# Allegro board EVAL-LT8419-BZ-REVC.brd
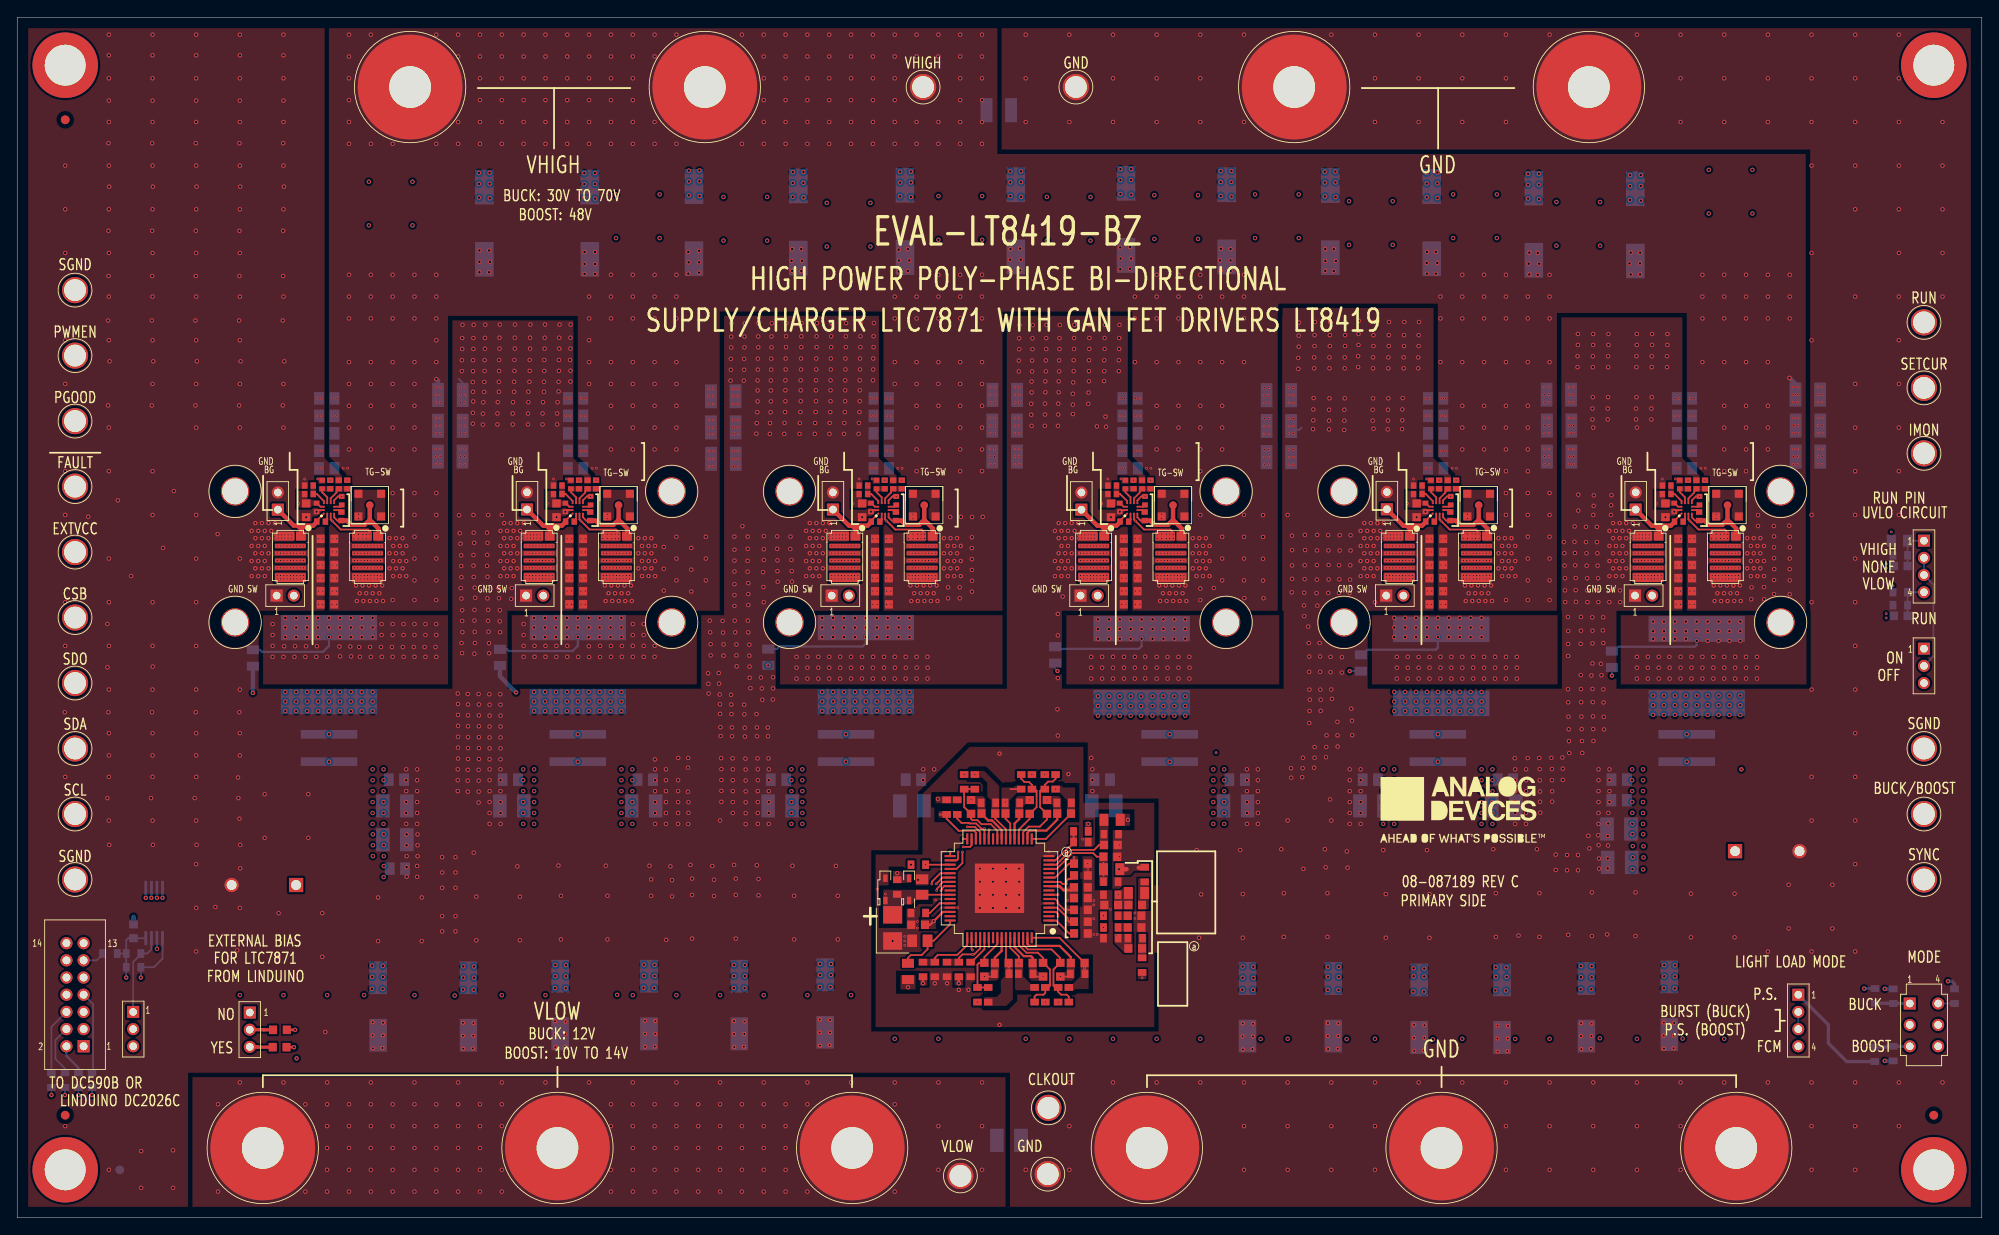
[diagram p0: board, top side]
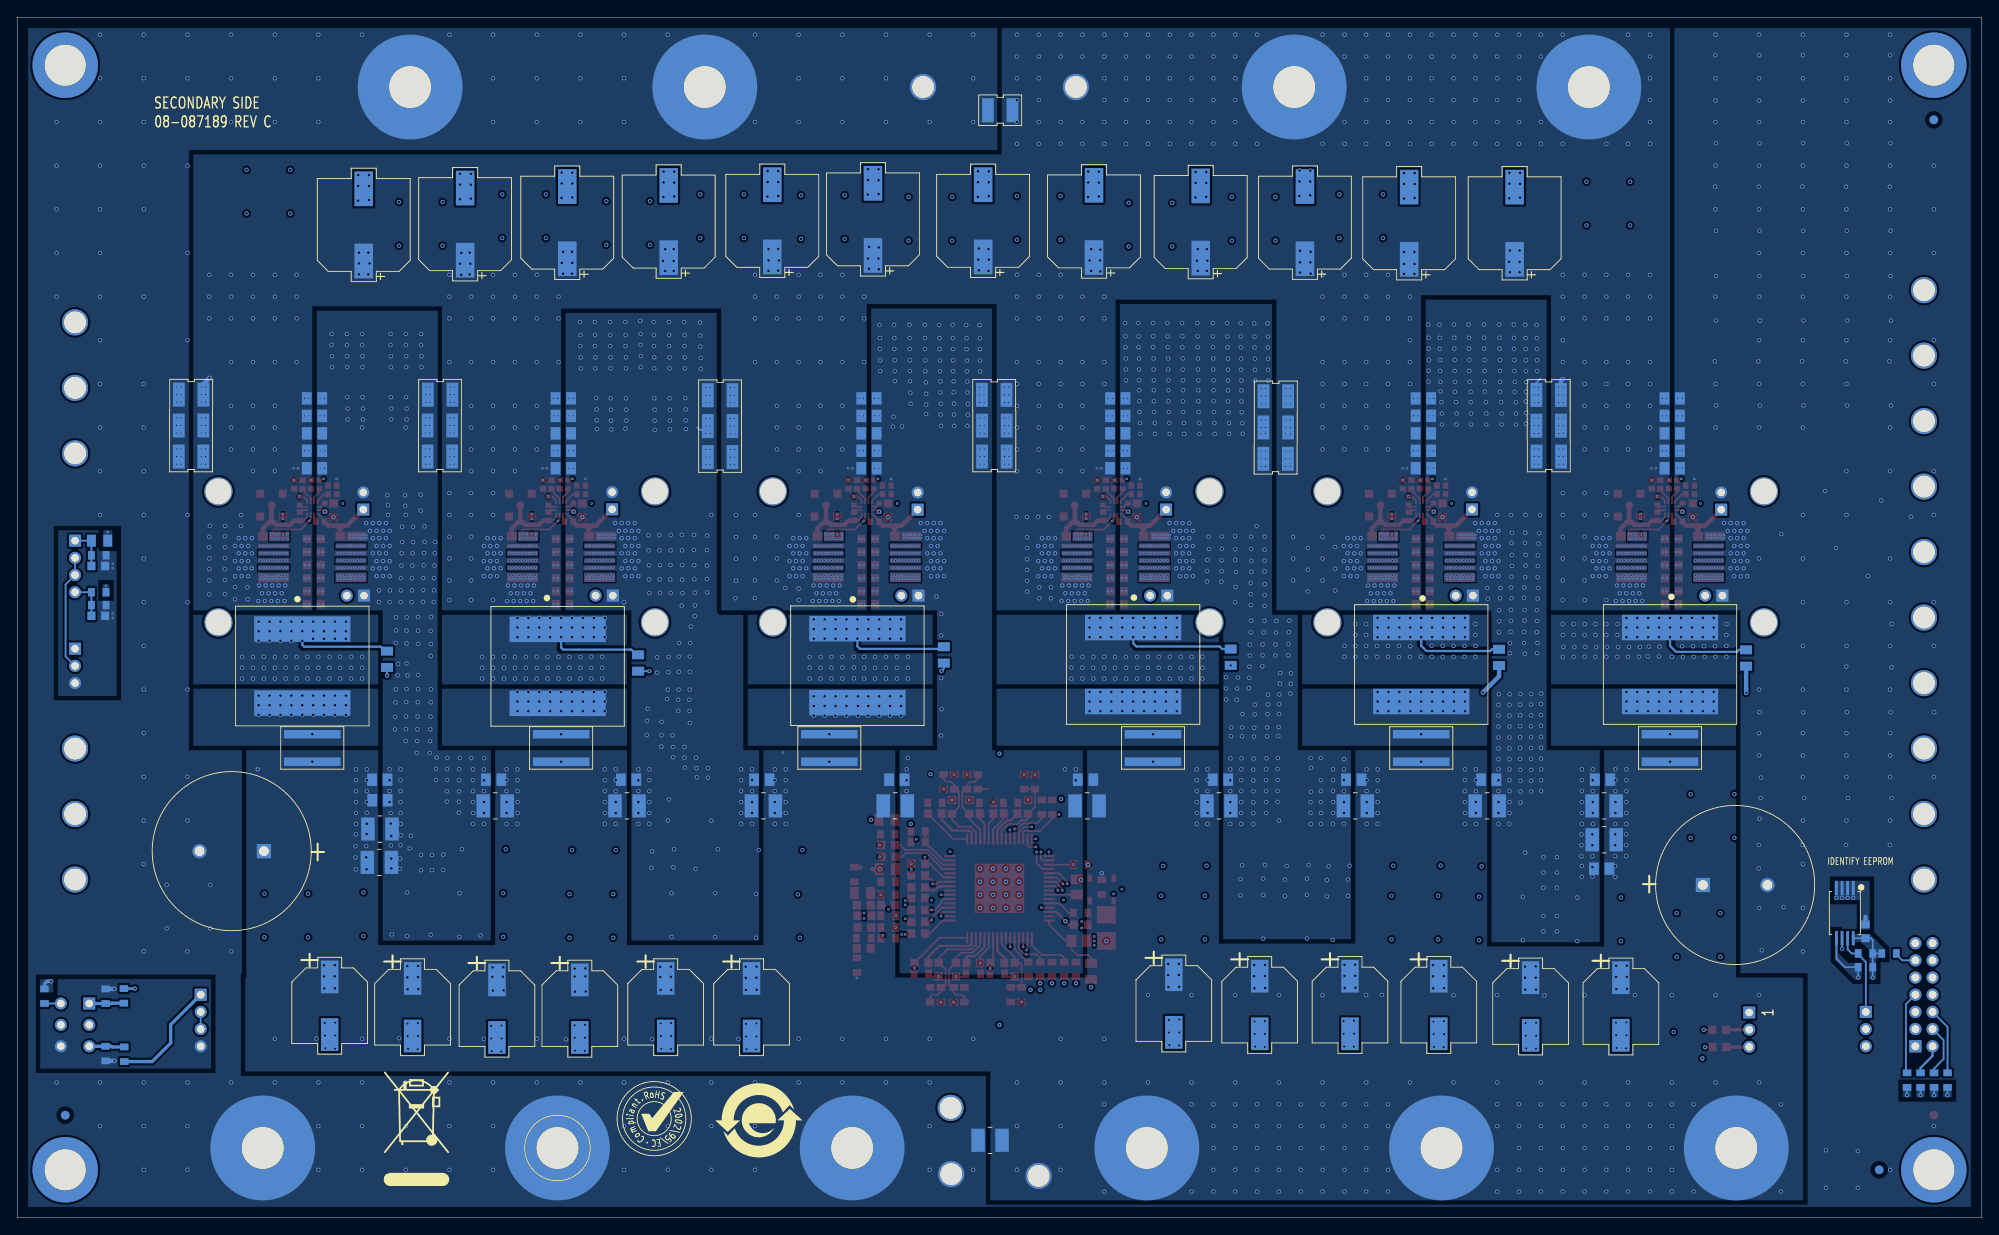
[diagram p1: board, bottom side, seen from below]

Outline 228.6 x 139.7 mm; copper layers: TOP, L2_PWR, L3_PWR, L4_PWR, L5_GND, L6_SIG, L7_SIG, BOTTOM. Coordinates in mm from the lower left corner of the outline.
Outline path: 0,139.7 0,0 228.6,0 228.6,139.7 0,139.7

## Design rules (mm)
constraint set DEFAULT: min track width 0.203
net group 3.3V_5V: nets 3.3V_5V SDO
net group _N108: nets _N108 _N113
net group SAC1: nets _N123 SDC1
net group SAC2: nets _N160 SDC2
net group SAC3: nets _N192 SDC3
net group SAC4: nets _N208 SDC4
net group SAC5: nets _N216 SDC5
net group SAC6: nets _N224 SDC6
net group _N125: nets _N125
net group _N126: nets _N126
net group _N161: nets _N161
net group _N162: nets _N162
net group _N193: nets _N193
net group _N194: nets _N194
net group _N209: nets _N209
net group _N210: nets _N210
net group _N217: nets _N217
net group _N218: nets _N218
net group _N225: nets _N225
net group _N226: nets _N226
net group CSB: nets _N101
net group PGOOD: nets _N69 _N265 _N266 _N267
net group PWM1: nets PWM1
net group PWM2: nets PWM2
net group PWM3: nets PWM3
net group PWM4: nets PWM4
net group PWM5: nets PWM5
net group PWM6: nets PWM6
net group SCL: nets _N100
net group SDA: nets _N102

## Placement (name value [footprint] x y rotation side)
C1  0.1UF  [C0402]  34.83 82.65 270 top
C2  1uF  [C0805]  105.3 38.49 90 top
C3  4.7uF  [C0603]  33.62 82.32 270 top
C4  10pF  [C0402]  35.48 85.33 270 top
C5  47PF  [C0603]  123.77 34.46 180 top
C6  0.01uF  [C0603]  130.02 33.78 180 top
C7  0.01uF  [C0603]  130.02 35.15 180 top
C8  0.22uF  [C0603]  36.1 77.48 0 top
C9  0.1uF  [C0603]  123.77 33.09 180 top
C10  4.7UF  [C0603]  123.77 37.2 0 top
C11  47pF  [C0603]  123.77 35.83 180 top
C12  10PF  [C0603]  123.77 39.84 0 top
C13  1uF  [C0805]  36.02 93.31 180 bottom
C14  0.1uF  [C0603]  119.83 47.81 90 top
C16  1uF  [C0805]  36.02 91.28 180 bottom
C17  0.1uF  [C0805]  44.24 40.63 0 bottom
C18  5100UF  [CPLRAD295D709H1240LD31]  32.45 38.72 180 bottom
C19  0.1uF  [C0805]  44.13 50.98 0 bottom
C20  5100UF  [CPLRAD295D709H1240LD31]  199.89 42.66 0 bottom
C21  4.7uF  [C1210-2]  43.94 43.99 0 bottom
C22  4.7UF  [C1210H110]  50.4 92.17 0 bottom
C23  4.7uF  [C1210-2]  43.95 47.93 0 bottom
C24  4.7UF  [C1210H110]  50.39 88.58 0 bottom
C25  47UF  [CPLSMSQ327H461]  42 24.59 270 bottom
C26  4.7UF  [C1210H110]  50.4 95.75 0 bottom
C27  47UF  [CPLSMSQ327H461]  52.5 24.59 270 bottom
C28  47UF  [CPLSMSQ327H461]  172.78 24.33 270 bottom
C29  47UF  [CPLSMSQ327H461]  73.52 24.76 270 bottom
C30  47UF  [CPLSMSQ327H461]  63.18 24.76 270 bottom
C31  4.7UF  [C0603]  104.83 34.1 180 top
C32  47UF  [CPLSMSQ327H461]  84.02 24.76 270 bottom
C33  47UF  [CPLSMSQ327H461]  94.01 24.93 270 bottom
C34  47UF  [CPLSMSQ327H461]  182.59 24.5 270 bottom
C35  47UF  [CPLSMSQ327H461]  192.24 24.68 270 bottom
C36  47UF  [CPLSMSQ327H461]  153.14 24.5 270 bottom
C37  47UF  [CPLSMSQ327H461]  143.15 24.5 270 bottom
C38  47UF  [CPLSMSQ327H461]  163.13 24.33 270 bottom
C39  1uF  [C0805]  105.03 32.23 180 top
C40  47UF  [CPLSMSQ406H425]  164.59 115.79 90 bottom
C41  47UF  [CPLSMSQ406H425]  176.48 115.62 90 bottom
C42  47UF  [CPLSMSQ406H425]  188.28 115.53 90 bottom
C43  0.1uF  [C0603]  30.57 21.87 180 top
C44  0.1uF  [C0603]  30.54 19.86 180 top
C45  47UF  [CPLSMSQ406H425]  129.03 116.18 90 bottom
C46  47UF  [CPLSMSQ406H425]  116.2 116.01 90 bottom
C47  47UF  [CPLSMSQ406H425]  103.3 115.94 90 bottom
C48  47UF  [CPLSMSQ406H425]  90.89 115.87 90 bottom
C49  47UF  [CPLSMSQ406H425]  78.76 115.8 90 bottom
C50  47UF  [CPLSMSQ406H425]  66.63 115.73 90 bottom
C51  47UF  [CPLSMSQ406H425]  152.79 115.92 90 bottom
C52  47UF  [CPLSMSQ406H425]  140.74 116.01 90 bottom
C53  47UF  [CPLSMSQ406H425]  54.36 115.73 90 bottom
C56  0.22uF  [C0603]  100.63 71.37 0 top
C65  4.7uF  [C1210-2]  115.4 9.02 0 bottom
C66  4.7UF  [C1210H110]  114.22 128.87 0 bottom
C148  TBD0603  [C0603]  123.77 41.21 0 top
C166  TBD0603  [C0603]  130.09 31.34 180 top
C167  TBD0603  [C0603]  130.09 36.4 180 top
C168  1uF  [C3528]  101.87 33.73 270 top
C169  0.1uF  [C0603]  13.54 33.34 90 bottom
C189  47PF  [C0603]  127.2 42.01 0 top
C194  TBD0603  [C0603]  219.16 70.05 180 bottom
C195  TBD0603  [C0603]  127.3 36.4 180 top
C196  TBD0603  [C0603]  127.25 43.38 0 top
C197  TBD0603  [C0603]  219.16 75.84 180 bottom
C700  0.1uF  [C0603]  123.77 38.45 0 top
C701  0.22uF  [C0402]  37.77 83.44 90 top
C702  0.22uF  [C0603]  36.1 71.38 0 top
C703  0.22uF  [C0603]  36.1 74.43 0 top
C704  0.22uF  [C0603]  36.1 75.95 0 top
C705  0.22uF  [C0603]  36.1 72.92 0 top
C708  1uF  [C0805]  36.02 89.25 180 bottom
C709  1uF  [C0805]  36.02 87.22 180 bottom
C710  1uF  [C0805]  36.02 95.34 180 bottom
C713  0.22uF  [C0603]  36.1 79 0 top
C715  0.1UF  [C0603]  121.82 47.04 180 top
C716  10pF  [C0402]  64.43 85.33 270 top
C717  4.7uF  [C0603]  62.75 82.32 270 top
C718  0.1UF  [C0402]  63.78 82.65 270 top
C719  0.22uF  [C0402]  66.72 83.44 90 top
C720  0.22uF  [C0603]  65.05 72.91 0 top
C721  0.22uF  [C0603]  65.05 71.38 0 top
C722  0.22uF  [C0603]  65.05 75.95 0 top
C723  0.22uF  [C0603]  65.05 74.43 0 top
C724  0.22uF  [C0603]  65.05 79 0 top
C725  0.22uF  [C0603]  65.05 77.48 0 top
C730  1uF  [C0805]  64.97 89.25 180 bottom
C731  1uF  [C0805]  64.97 91.28 180 bottom
C732  1uF  [C0805]  64.97 93.31 180 bottom
C733  1uF  [C0805]  64.97 95.34 180 bottom
C734  1uF  [C0805]  64.97 87.22 180 bottom
C739  4.7UF  [C1210H110]  82.18 88.32 0 bottom
C740  4.7UF  [C1210H110]  82.16 91.96 0 bottom
C741  4.7UF  [C1210H110]  82.15 95.59 0 bottom
C742  0.1UF  [C0603]  115.8 47.04 0 top
C743  0.1uF  [C0603]  117.82 47.81 90 top
C744  0.1uF  [C0805]  57.38 50.98 180 bottom
C745  0.1uF  [C0805]  73.08 50.98 0 bottom
C746  4.7uF  [C1210-2]  57.56 47.93 180 bottom
C747  4.7uF  [C1210-2]  72.9 47.93 0 bottom
C750  10pF  [C0402]  99.99 85.33 270 top
C751  4.7uF  [C0603]  98.32 82.32 270 top
C752  0.1UF  [C0402]  99.35 82.65 270 top
C753  0.22uF  [C0402]  102.28 83.44 90 top
C754  0.22uF  [C0603]  129.57 71.38 0 top
C755  0.22uF  [C0603]  100.62 75.95 0 top
C757  0.22uF  [C0603]  100.62 74.43 0 top
C758  0.22uF  [C0603]  100.62 72.91 0 top
C759  0.22uF  [C0603]  129.57 75.95 0 top
C764  1uF  [C0805]  100.54 89.25 180 bottom
C765  1uF  [C0805]  100.54 91.28 180 bottom
C766  1uF  [C0805]  100.54 95.34 180 bottom
C767  1uF  [C0805]  100.54 93.31 180 bottom
C768  1uF  [C0805]  100.54 87.22 180 bottom
C773  4.7UF  [C1210H110]  114.9 88.58 0 bottom
C774  4.7UF  [C1210H110]  114.9 92.17 0 bottom
C775  4.7UF  [C1210H110]  114.92 95.76 0 bottom
C776  0.1UF  [C0603]  113.01 47.04 180 top
C777  0.1uF  [C0805]  88.59 50.98 180 bottom
C778  0.1uF  [C0805]  104.29 50.98 0 bottom
C779  4.7uF  [C1210-2]  88.77 47.93 180 bottom
C780  4.7uF  [C1210-2]  104.11 47.93 0 bottom
C783  0.1uF  [C0603]  110.99 47.81 90 top
C800  10pF  [C0402]  128.94 85.33 270 top
C801  4.7uF  [C0603]  127.27 82.32 270 top
C802  0.1UF  [C0402]  128.3 82.65 270 top
C803  0.22uF  [C0402]  131.23 83.44 90 top
C804  0.22uF  [C0603]  165.13 77.48 0 top
C805  0.22uF  [C0603]  129.57 79 0 top
C806  0.22uF  [C0603]  129.57 77.48 0 top
C807  0.22uF  [C0603]  165.13 79 0 top
C808  0.22uF  [C0603]  129.57 72.91 0 top
C809  0.22uF  [C0603]  129.57 74.43 0 top
C814  1uF  [C0805]  129.49 91.28 180 bottom
C815  1uF  [C0805]  129.49 89.25 180 bottom
C816  1uF  [C0805]  129.49 87.22 180 bottom
C817  1uF  [C0805]  129.49 95.34 180 bottom
C818  1uF  [C0805]  129.49 93.31 180 bottom
C823  4.7UF  [C1210H110]  146.81 92.13 0 bottom
C824  4.7UF  [C1210H110]  146.81 88.51 0 bottom
C825  4.7UF  [C1210H110]  146.81 95.71 0 bottom
C826  0.1UF  [C0603]  114.56 29.65 180 top
C827  0.1uF  [C0603]  112.54 28.87 270 top
C828  0.1uF  [C0805]  126.25 50.98 180 bottom
C829  0.1uF  [C0805]  141.95 50.98 0 bottom
C830  4.7uF  [C1210-2]  126.43 47.93 180 bottom
C831  4.7uF  [C1210-2]  141.77 47.93 0 bottom
C834  10pF  [C0402]  164.51 85.33 270 top
C835  4.7uF  [C0603]  162.83 82.32 270 top
C836  0.1UF  [C0402]  163.86 82.65 270 top
C837  0.22uF  [C0402]  166.8 83.44 90 top
C838  0.22uF  [C0603]  165.13 74.43 0 top
C839  0.22uF  [C0603]  165.13 71.38 0 top
C840  0.22uF  [C0603]  194.08 71.38 0 top
C841  0.22uF  [C0603]  165.13 72.91 0 top
C842  0.22uF  [C0603]  194.08 74.43 0 top
C843  0.22uF  [C0603]  194.08 75.95 0 top
C848  1uF  [C0805]  165.06 93.31 180 bottom
C849  1uF  [C0805]  165.06 91.28 180 bottom
C850  1uF  [C0805]  165.06 89.25 180 bottom
C851  1uF  [C0805]  165.06 87.22 180 bottom
C852  1uF  [C0805]  165.06 95.34 180 bottom
C857  4.7UF  [C1210H110]  179.42 92.19 0 bottom
C858  4.7UF  [C1210H110]  179.42 88.58 0 bottom
C859  4.7UF  [C1210H110]  179.39 95.78 0 bottom
C860  0.1UF  [C0603]  117.35 29.65 0 top
C861  0.1uF  [C0603]  119.37 28.87 270 top
C862  0.1uF  [C0805]  157.46 50.98 180 bottom
C863  0.1uF  [C0805]  173.16 50.98 0 bottom
C864  4.7uF  [C1210-2]  157.64 47.93 180 bottom
C865  4.7uF  [C1210-2]  172.98 47.93 0 bottom
C868  10pF  [C0402]  193.46 85.33 270 top
C869  4.7uF  [C0603]  191.78 82.32 270 top
C870  0.1UF  [C0402]  192.81 82.65 270 top
C871  0.22uF  [C0402]  195.75 83.44 90 top
C873  0.22uF  [C0603]  194.08 77.48 0 top
C874  0.22uF  [C0603]  194.08 79 0 top
C875  0.22uF  [C0603]  165.13 75.95 0 top
C876  0.22uF  [C0603]  194.08 72.91 0 top
C877  0.22uF  [C0603]  100.62 79 0 top
C878  0.22uF  [C0603]  100.62 77.48 0 top
C883  1uF  [C0805]  194.01 93.31 180 bottom
C884  1uF  [C0805]  194.01 91.28 180 bottom
C885  1uF  [C0805]  194.01 89.25 180 bottom
C886  1uF  [C0805]  194.01 87.22 180 bottom
C887  1uF  [C0805]  194.01 95.34 180 bottom
C892  4.7UF  [C1210H110]  208.37 88.58 0 bottom
C893  4.7UF  [C1210H110]  208.37 92.19 0 bottom
C894  4.7UF  [C1210H110]  208.35 95.79 0 bottom
C895  0.1uF  [C0603]  121.38 28.87 270 top
C896  0.1UF  [C0603]  123.4 29.65 180 top
C897  0.1uF  [C0805]  186.41 50.98 180 bottom
C898  0.1uF  [C0805]  186.39 48.59 180 bottom
C899  4.7uF  [C1210-2]  186.39 45.24 180 bottom
C900  4.7uF  [C1210-2]  186.45 41.36 180 bottom
D12  PMEG2020EJ,115  [SOD323F_B]  103.79 38.22 90 top
D13  PMEG2020EJ,115  [SOD323F_B]  101.02 38.22 90 top
E1  2501-2-00-80-00-00-07-0  [CNMILLMAX2501]  6.73 77.46 0 top
E2  2501-2-00-80-00-00-07-0  [CNMILLMAX2501]  221.87 88.95 0 top
E3  2501-2-00-80-00-00-07-0  [CNMILLMAX2501]  119.99 12.8 0 top
E4  2501-2-00-80-00-00-07-0  [CNMILLMAX2501]  221.87 46.98 0 top
E5  2501-2-00-80-00-00-07-0  [CNMILLMAX2501]  221.87 96.57 90 top
E9  2501-2-00-80-00-00-07-0  [CNMILLMAX2501]  6.73 85.08 0 top
E11  2501-2-00-80-00-00-07-0  [CNMILLMAX2501]  105.41 131.57 0 top
E14  2501-2-00-80-00-00-07-0  [CNMILLMAX2501]  221.87 54.6 0 top
E15  2501-2-00-80-00-00-07-0  [CNMILLMAX2501]  6.73 39.36 0 top
E19  2501-2-00-80-00-00-07-0  [CNMILLMAX2501]  109.75 4.87 90 top
E20  2501-2-00-80-00-00-07-0  [CNMILLMAX2501]  123.19 131.57 0 top
E21  2501-2-00-80-00-00-07-0  [CNMILLMAX2501]  221.87 39.36 0 top
E22  2501-2-00-80-00-00-07-0  [CNMILLMAX2501]  6.73 100.32 0 top
E25  2501-2-00-80-00-00-07-0  [CNMILLMAX2501]  6.73 107.94 0 top
E29  2501-2-00-80-00-00-07-0  [CNMILLMAX2501]  6.73 46.98 0 top
E30  2501-2-00-80-00-00-07-0  [CNMILLMAX2501]  6.73 62.22 0 top
E31  2501-2-00-80-00-00-07-0  [CNMILLMAX2501]  6.73 69.84 0 top
E32  2501-2-00-80-00-00-07-0  [CNMILLMAX2501]  6.73 54.6 0 top
E33  2501-2-00-80-00-00-07-0  [CNMILLMAX2501]  6.73 92.7 0 top
E34  2501-2-00-80-00-00-07-0  [CNMILLMAX2501]  221.87 104.19 0 top
E40  2501-2-00-80-00-00-07-0  [CNMILLMAX2501]  119.92 5.08 0 top
J1  KFH-032-10ET  [CNPEMKFH-032]  80.01 131.57 0 top
J2  KFH-032-10ET  [CNPEMKFH-032]  165.73 8.13 0 top
J3  0734152063  [CNSMASQ136H203]  105.54 82.92 0 top
J4  0734152063  [CNSMASQ136H203]  134.49 82.92 0 top
J5  KFH-032-10ET  [CNPEMKFH-032]  131.44 8.13 0 top
J6  87831-1420  [CNMOLEX87831-1420]  7.73 19.96 90 top
J7  KFH-032-10ET  [CNPEMKFH-032]  28.57 8.13 0 top
J8  KFH-032-10ET  [CNPEMKFH-032]  62.87 8.13 0 top
J9  KFH-032-10ET  [CNPEMKFH-032]  200.03 8.13 0 top
J10  KFH-032-10ET  [CNPEMKFH-032]  97.15 8.13 0 top
J11  KFH-032-10ET  [CNPEMKFH-032]  148.59 131.57 0 top
J12  KFH-032-10ET  [CNPEMKFH-032]  45.72 131.57 0 top
J13  KFH-032-10ET  [CNPEMKFH-032]  182.88 131.57 0 top
J14  0734152063  [CNSMASQ136H203]  199.01 82.92 0 top
J15  0734152063  [CNSMASQ136H203]  41.03 82.92 0 top
J16  0734152063  [CNSMASQ136H203]  170.06 82.92 0 top
J17  0734152063  [CNSMASQ136H203]  69.98 82.92 0 top
JP1  62000311121  [CNTHMHDR1X3L236W79H244]  27.06 23.89 270 top
JP3  62000411121  [CNTHMHDR1X4L315W79H250]  207.25 25.96 270 top
JP4  62000311121  [CNTHMHDR1X3L236W79H244]  221.87 66.22 270 top
JP21  62000311121  [CNTHMHDR1X3L236W79H244]  13.5 23.96 270 top
L1  2.2UH  [LSML528W591H512]  36.28 64.38 270 bottom
L2  2.2UH  [LSML528W591H512]  65.23 64.38 270 bottom
L3  2.2UH  [LSML528W591H512]  98.75 64.38 270 bottom
L4  2.2UH  [LSML528W591H512]  130.84 64.24 270 bottom
L5  2.2UH  [LSML528W591H512]  165.71 64.16 270 bottom
L6  2.2UH  [LSML528W591H512]  195.43 64.2 270 bottom
NOREF  -  []  -53.73 -187.67 0 top
NOREF#2  -  []  126.47 132.06 0 top
NOREF#3  -  []  0 139.7 0 top
NOREF#4  -  []  228.6 0 0 top
NOREF#5  -  []  0 0 0 top
NOREF#6  -  []  407.69 -27.16 90 top
NOREF#7  -  []  278.79 -33.19 0 top
NOREF#8  -  []  0 0 0 top
NOREF#9  -  []  298.87 -37.32 0 top
NOREF#10  -  []  297.7 -27.16 0 top
NOREF#11  -  []  240.05 136.6 0 top
NOREF#12  -  []  -9.21 146.75 270 top
NOREF#13  -  []  0 139.7 0 top
NOREF#14  -  []  -52.58 -187.96 0 top
NOREF#15  -  [unnamed#2]  223.01 11.94 180 top
NOREF#16  -  []  335.3 -28.75 0 top
NOREF#17  -  []  5.59 5.59 0 top
NOREF#18  -  []  77.38 136.34 0 top
NOREF#19  -  []  168.2 47.47 0 top
NOREF#20  -  []  228.6 0 90 top
NOREF#21  -  []  -190.71 -153.43 0 top
NOREF#22  -  [unnamed#2]  5.59 11.94 180 top
NOREF#23  -  []  5.59 5.59 0 top
NOREF#24  -  []  118.2 37.25 0 top
NOREF#25  -  [unnamed#2]  5.59 127.76 0 top
NOREF#26  -  []  407.69 -51.29 90 top
NOREF#27  -  [unnamed#2]  223.01 134.11 180 bottom
NOREF#28  -  [unnamed#2]  5.59 134.11 180 bottom
NOREF#29  -  []  154.48 11.54 180 bottom
NOREF#30  -  [unnamed#2]  11.94 5.59 0 bottom
NOREF#31  -  [unnamed#2]  5.59 127.76 180 bottom
NOREF#32  -  [unnamed#2]  5.59 5.59 180 bottom
NOREF#33  -  []  142.31 11.34 180 bottom
NOREF#34  -  [unnamed#2]  223.01 11.94 0 bottom
NOREF#35  -  []  172.87 20.59 180 bottom
NOREF#36  -  [unnamed#2]  223.01 5.59 180 bottom
P1  62000211121  [CNTHMHDR1X2L157W79H250]  30.33 82.4 90 top
P2  62000211121  [CNTHMHDR1X2L157W79H250]  30.19 72.4 0 top
P3  62000211121  [CNTHMHDR1X2L157W79H250]  59.32 82.42 90 top
P4  62000211121  [CNTHMHDR1X2L157W79H250]  59.21 72.4 0 top
P5  62000211121  [CNTHMHDR1X2L157W79H250]  94.92 82.41 90 top
P6  62000211121  [CNTHMHDR1X2L157W79H250]  94.78 72.4 0 top
P7  62000211121  [CNTHMHDR1X2L157W79H250]  123.82 82.4 90 top
P8  62000211121  [CNTHMHDR1X2L157W79H250]  123.73 72.4 0 top
P9  62000211121  [CNTHMHDR1X2L157W79H250]  159.37 82.44 90 top
P10  62000211121  [CNTHMHDR1X2L157W79H250]  159.29 72.4 0 top
P11  62000211121  [CNTHMHDR1X2L157W79H250]  188.33 82.41 90 top
P12  62000211121  [CNTHMHDR1X2L157W79H250]  188.24 72.4 0 top
P16  9774010243R  [CNWURTH9774010243R]  89.87 69.28 90 top
P17  9774010243R  [CNWURTH9774010243R]  89.87 84.52 90 top
P18  9774010243R  [CNWURTH9774010243R]  140.67 69.28 90 top
P19  9774010243R  [CNWURTH9774010243R]  140.67 84.52 90 top
P20  9774010243R  [CNWURTH9774010243R]  76.15 69.28 90 top
P21  9774010243R  [CNWURTH9774010243R]  25.35 69.28 90 top
P22  9774010243R  [CNWURTH9774010243R]  76.15 84.52 90 top
P23  9774010243R  [CNWURTH9774010243R]  25.35 84.52 90 top
P24  9774010243R  [CNWURTH9774010243R]  205.19 69.28 90 top
P25  9774010243R  [CNWURTH9774010243R]  154.39 69.28 90 top
P26  9774010243R  [CNWURTH9774010243R]  205.19 84.52 90 top
P27  9774010243R  [CNWURTH9774010243R]  154.39 84.52 90 top
P28  62000411121  [CNTHMHDR1X4L315W79H250]  221.87 78.79 270 top
Q1  EPC2361  [DIE7_5X3]  40.77 76.9 270 top
Q2  EPC2361  [DIE7_5X3]  31.78 76.9 270 top
Q3  EPC2361  [DIE7_5X3]  69.72 76.9 270 top
Q4  EPC2361  [DIE7_5X3]  60.73 76.9 270 top
Q5  EPC2361  [DIE7_5X3]  105.29 76.9 270 top
Q6  EPC2361  [DIE7_5X3]  96.3 76.9 270 top
Q7  EPC2361  [DIE7_5X3]  134.24 76.9 270 top
Q8  EPC2361  [DIE7_5X3]  125.25 76.9 270 top
Q9  EPC2361  [DIE7_5X3]  169.8 76.9 270 top
Q10  EPC2361  [DIE7_5X3]  160.82 76.9 270 top
Q11  EPC2361  [DIE7_5X3]  198.75 76.9 270 top
Q12  EPC2361  [DIE7_5X3]  189.77 76.9 270 top
R1  3.01M  [R0805]  127.35 40.56 0 top
R2  210K  [R0805]  127.4 46.31 180 top
R3  2  [R0402]  37.73 81.63 270 top
R4  1  [R0402]  35.36 81.01 180 top
R5  10K  [R0603]  225.42 25.79 270 bottom
R6  10K  [R0603]  216.18 25.83 90 bottom
R7  10K  [R0603]  105.4 28.9 90 top
R8  10K  [R0603]  127.3 44.63 180 top
R9  10K  [R0603]  123.77 43.73 180 top
R10  2K  [R0603]  127.25 33.78 180 top
R11  14.0K  [R0603]  127.25 35.15 180 top
R12  100  [R0603]  8.7 16.02 270 bottom
R13  10K  [R0603]  216.14 19.03 270 bottom
R15  130K  [R0603]  123.77 44.97 180 top
R17  30.1K  [R0603]  106.77 28.9 270 top
R18  100K  [R0603]  104.86 41.09 0 top
R20  0  [R0603]  104.86 35.47 180 top
R29  2.2  [R0805]  103.65 28.67 90 top
R36  48.7K  [R0603]  127.25 39.12 180 top
R44  62K  [R0603]  110.94 28.9 90 top
R123  100K  [R0603]  108.14 47.79 270 top
R414  TBD0603  [R0603]  102.4 38.49 270 top
R415  100  [R0603]  5.56 16.02 270 bottom
R416  100  [R0603]  3.99 16.02 270 bottom
R417  1K  [R0603]  7.13 16.02 270 bottom
R418  10K  [R0603]  109.39 47.79 270 top
R425  2.49K  [R0603]  218.31 25.79 90 bottom
R426  0  [R0603]  130.89 29.4 90 top
R427  91K  [R0603]  130.09 32.54 180 top
R428  10K  [R0603]  127.25 32.54 180 top
R429  0  [R0603]  131.19 39.94 270 top
R430  12.7K  [R0603]  127.25 37.59 180 top
R431  499K  [R0805]  130.24 37.79 180 top
R438  2.49K  [R0603]  218.31 19.11 270 bottom
R439  4.99K  [R0603]  10.8 30.76 180 bottom
R440  4.99K  [R0603]  13.54 30.76 0 bottom
R441  4.99K  [R0603]  13.54 29.16 0 bottom
R456  TBD0603  [R0603]  109.57 28.9 90 top
R457  TBD0603  [R0603]  108.19 28.9 90 top
R458  TBD0603  [R0603]  120.83 50.73 90 top
R459  TBD0603  [R0603]  116.83 50.73 90 top
R460  TBD0603  [R0603]  111.43 50.73 270 top
R461  TBD0603  [R0603]  112.98 25.95 90 top
R462  TBD0603  [R0603]  118.38 25.95 270 top
R463  TBD0603  [R0603]  122.37 25.95 270 top
R464  TBD0805  [R0805]  219.01 78.79 0 bottom
R465  TBD0603  [R0603]  219.11 72.79 0 bottom
R466  TBD0603  [R0603]  219.11 71.29 180 bottom
R468  TBD0603  [R0603]  219.11 77.09 180 bottom
R701  48.7K  [R0402]  33.95 85.2 0 top
R702  0  [R0402]  33.95 84.21 0 top
R703  0  [R0402]  36.43 85.33 270 top
R704  0  [R0402]  38.41 85.33 270 top
R705  48.7K  [R0402]  37.42 85.33 90 top
R706  5.49K  [R0805]  27.43 65.13 270 bottom
R707  549  [R0603]  121.82 48.28 180 top
R708  499  [R0603]  119.57 50.73 270 top
R709  0.001  [R1225H28]  36.28 54.67 270 bottom
R710  0  [R0402]  65.38 85.33 270 top
R711  0  [R0402]  62.9 84.21 0 top
R712  48.7K  [R0402]  62.9 85.2 0 top
R713  0  [R0402]  67.36 85.33 270 top
R714  48.7K  [R0402]  66.37 85.33 90 top
R715  2  [R0402]  66.68 81.63 270 top
R716  1  [R0402]  64.31 81.01 180 top
R717  5.49K  [R0805]  56.17 65.21 270 bottom
R718  549  [R0603]  115.8 48.28 0 top
R719  499  [R0603]  118.07 50.73 270 top
R720  0.001  [R1225H28]  65.23 54.67 270 bottom
R721  0  [R0402]  100.94 85.33 270 top
R722  0  [R0402]  98.46 84.21 0 top
R723  48.7K  [R0402]  98.46 85.2 0 top
R724  0  [R0402]  102.92 85.33 270 top
R725  48.7K  [R0402]  101.93 85.33 90 top
R726  2  [R0402]  102.24 81.63 270 top
R727  1  [R0402]  99.88 81.01 180 top
R728  5.49K  [R0805]  87.39 65.23 270 bottom
R729  499  [R0603]  110.19 50.73 270 top
R730  549  [R0603]  113.01 48.28 180 top
R731  0.001  [R1225H28]  96.44 54.67 270 bottom
R800  0  [R0402]  129.89 85.33 270 top
R801  0  [R0402]  127.41 84.21 0 top
R802  48.7K  [R0402]  127.41 85.2 0 top
R803  0  [R0402]  131.88 85.33 270 top
R804  48.7K  [R0402]  130.89 85.33 90 top
R805  2  [R0402]  131.19 81.63 270 top
R806  1  [R0402]  128.83 81.01 180 top
R807  5.49K  [R0805]  120.78 65.5 270 bottom
R809  499  [R0603]  111.74 25.95 90 top
R810  549  [R0603]  114.56 28.4 180 top
R811  0.001  [R1225H28]  134.1 54.67 270 bottom
R812  0  [R0402]  165.46 85.33 270 top
R813  0  [R0402]  162.98 84.21 0 top
R814  48.7K  [R0402]  162.98 85.2 0 top
R815  0  [R0402]  167.44 85.33 270 top
R816  48.7K  [R0402]  166.45 85.33 90 top
R817  2  [R0402]  166.76 81.63 270 top
R818  1  [R0402]  164.39 81.01 180 top
R819  5.49K  [R0805]  156.35 64.56 270 bottom
R820  499  [R0603]  119.62 25.95 90 top
R821  0.001  [R1225H28]  165.31 54.67 270 bottom
R822  549  [R0603]  117.35 28.4 0 top
R823  0  [R0402]  194.41 85.33 270 top
R824  0  [R0402]  191.93 84.21 0 top
R825  48.7K  [R0402]  191.93 85.2 0 top
R826  0  [R0402]  196.39 85.33 270 top
R827  48.7K  [R0402]  195.4 85.33 90 top
R828  2  [R0402]  195.71 81.63 270 top
R829  1  [R0402]  193.34 81.01 180 top
R830  5.49K  [R0805]  185.56 64.99 270 bottom
R831  499  [R0603]  121.12 25.95 90 top
R832  0.001  [R1225H28]  194.26 54.67 270 bottom
R833  549  [R0603]  123.4 28.4 180 top
S1  JS202011CQN  [SWTHL354W142H217]  220.22 24.94 270 top
U1  LT8419ACBZ-R7  [WLCSP16_12P_1_67X1_67H0_56]  36.28 82.54 90 top
U2  LT8419ACBZ-R7  [WLCSP16_12P_1_67X1_67H0_56]  65.23 82.54 90 top
U3  LT8419ACBZ-R7  [WLCSP16_12P_1_67X1_67H0_56]  100.79 82.54 90 top
U4  LT8419ACBZ-R7  [WLCSP16_12P_1_67X1_67H0_56]  129.74 82.54 90 top
U5  LT8419ACBZ-R7  [WLCSP16_12P_1_67X1_67H0_56]  165.31 82.54 90 top
U6  LT8419ACBZ-R7  [WLCSP16_12P_1_67X1_67H0_56]  194.26 82.54 90 top
U7  LTC7871ELWE#PBF  [QFP64_10X10_PAD5_74X5_74_05-08-1982]  114.3 38.34 90 top
U8  24LC025-I/ST  [TSSOP8]  15.94 35.46 0 bottom

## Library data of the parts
C1 C701 C718 C719 C752 C753 C802 C803 C836 C837 C870 C871 = CAP: User Part Number: UPN; Tolerance: 10; alternate symbols: (C0402); tolerance: 10
C2 C13 C16 C39 C708-C710 C730-C734 C764-C768 C814-C818 C848-C852 C883-C887 = CAP: User Part Number: UPN; Tolerance: 10; alternate symbols: (C0805); tolerance: 10
C3 C5-C10 C14 C31 C43 C44 C56 C169 C189 C700 C702-C705 C713 C715 C717 C720-C725 C742 C743 C751 C754 C755 C757-C759 C776 C783 C801 C804-C809 C826 C827 C835 C838-C843 C860 C861 C869 C873-C878 C895 C896 = CAP: User Part Number: UPN; Tolerance: 10; alternate symbols: (C0603); tolerance: 10
C4 C716 C750 C800 C834 C868 = CAP: User Part Number: UPN; Tolerance: 5; alternate symbols: (C0402); tolerance: 5
C11 = CAP: User Part Number: UPN; Tolerance: 5; alternate symbols: (C0603); tolerance: 5
C12 = CAP: User Part Number: UPN; Tolerance: 1; alternate symbols: (C0603); tolerance: 1
C17 C19 C744 C745 C777 C778 C828 C829 C862 C863 C897 C898 = CAP: User Part Number: UPN; Tolerance: 5; alternate symbols: (C0805); tolerance: 5
C18 C20 = CAPP: User Part Number: UPN; Tolerance: 20; alternate symbols: (CPLRAD295D709H1240LD31); tolerance: 20
C21 C23 C65 C746 C747 C779 C780 C830 C831 C864 C865 C899 C900 = CAP: Tolerance: 10; User Part Number: UPN; alternate symbols: (C1210-2); tolerance: 10
C22 C24 C26 C66 C739-C741 C773-C775 C823-C825 C857-C859 C892-C894 = CAP: Tolerance: 10; User Part Number: UPN; alternate symbols: (C1210H110); tolerance: 10
C25 C27-C30 C32-C38 = CAPP: User Part Number: UPN; Tolerance: 20; alternate symbols: (CPLSMSQ327H461); tolerance: 20
C40-C42 C45-C53 = CAPP: User Part Number: UPN; Tolerance: 20; alternate symbols: (CPLSMSQ406H425); tolerance: 20
C148 C166 C167 C194-C197 = CAP: User Part Number: UPN; alternate symbols: (C0603)
C168 = CAPP: User Part Number: UPN; Tolerance: 10; alternate symbols: (C3528); tolerance: 10
D12 D13 = DIOSCHOTTKY: User Part Number: UPN; Tolerance: N/A; alternate symbols: (SOD323F_B); tolerance: N/A
E1-E5 E9 E11 E14 E15 E19-E22 E25 E29-E34 E40 = CNTP1P: User Part Number: UPN; Tolerance: N/A; alternate symbols: (CNMILLMAX2501); tolerance: N/A
J1 J2 J5 J7-J13 = CN1P: User Part Number: UPN; Tolerance: N/A; alternate symbols: (CNPEMKFH-032); tolerance: N/A
J3 J4 J14-J17 = CNBNC5P: Tolerance: N/A; User Part Number: UPN; alternate symbols: (CNSMASQ136H203); tolerance: N/A
J6 = CN14P: Tolerance: N/A; User Part Number: UPN; alternate symbols: (CNMOLEX87831-1420); tolerance: N/A
JP1 JP4 JP21 = CN3P: User Part Number: UPN; Tolerance: N/A; alternate symbols: (CNTHMHDR1X3L236W79H244); tolerance: N/A
JP3 P28 = CN4P: Tolerance: N/A; User Part Number: UPN; alternate symbols: (CNTHMHDR1X4L315W79H250); tolerance: N/A
L1-L6 = IND: Tolerance: 20; User Part Number: UPN; alternate symbols: (LSML528W591H512); tolerance: 20
P1-P12 = CN2P: User Part Number: UPN; Tolerance: N/A; alternate symbols: (CNTHMHDR1X2L157W79H250); tolerance: N/A
P16-P27 = CN1P: Tolerance: N/A; User Part Number: UPN; alternate symbols: (CNWURTH9774010243R); tolerance: N/A
Q1-Q12 = TRANNGANFET7P_V3: User Part Number: UPN; Tolerance: N/A; alternate symbols: (DIE7_5X3); tolerance: N/A
R1 R29 R431 R706 R717 R728 R807 R819 R830 = RES: User Part Number: UPN; Tolerance: 1; alternate symbols: (R0805); tolerance: 1
R2 = RES: User Part Number: UPN; Tolerance: 0.1; alternate symbols: (R0805); tolerance: 0.1
R3 R701 R705 R712 R714 R715 R723 R725 R726 R802 R804 R805 R814 R816 R817 R825 R827 R828 = RES: User Part Number: UPN; Tolerance: 1; alternate symbols: (R0402); tolerance: 1
R4 R716 R727 = RES: User Part Number: UPN; Tolerance: 5; alternate symbols: (R0402); tolerance: 5
R5-R7 R9-R13 R15 R17 R18 R36 R123 R415-R418 R425 R427 R428 R430 R438-R441 R707 R708 R718 R719 R729 R730 R809 R810 R820 R822 R831 R833 = RES: User Part Number: UPN; Tolerance: 1; alternate symbols: (R0603); tolerance: 1
R8 = RES: User Part Number: UPN; Tolerance: 0.1; alternate symbols: (R0603); tolerance: 0.1
R20 R426 R429 = RES: User Part Number: UPN; Tolerance: JUMPER; alternate symbols: (R0603); tolerance: JUMPER
R44 = RES: User Part Number: UPN; Tolerance: 5; alternate symbols: (R0603); tolerance: 5
R414 R456-R463 R465 R466 R468 = RES: User Part Number: UPN; alternate symbols: (R0603)
R464 = RES: User Part Number: UPN; alternate symbols: (R0805)
R702-R704 R710 R711 R713 R721 R722 R724 R800 R801 R803 R812 R813 R815 R823 R824 R826 = RES: User Part Number: UPN; Tolerance: N/A; alternate symbols: (R0402); tolerance: N/A
R709 R720 R731 R811 R821 R832 = RES: User Part Number: UPN; Tolerance: 5; alternate symbols: (R1225H28); tolerance: 5
R806 R818 R829 = RES: User Part Number: UPN; alternate symbols: (R0402)
S1 = SWDPDT_V5: Tolerance: N/A; User Part Number: UPN; alternate symbols: (SWTHL354W142H217); tolerance: N/A
U1-U6 = ADLT8419: User Part Number: UPN; Tolerance: N/A; alternate symbols: (WLCSP16_12P_1_67X1_67H0_56); tolerance: N/A
U7 = ADLTC7871: User Part Number: UPN; Tolerance: N/A; alternate symbols: (QFP64_10X10_PAD5_74X5_74_05-08-1982); tolerance: N/A
U8 = IC24XX02: Tolerance: N/A; User Part Number: UPN; alternate symbols: (TSSOP8); tolerance: N/A

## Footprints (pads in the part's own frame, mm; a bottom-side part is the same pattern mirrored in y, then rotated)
C0402
  rect 0.584x0.66 smd: 1(-0.5,0) 2(0.5,0)
C0603
  rect 0.94x0.991 smd: 1(-0.8,0) 2(0.8,0)
C0805
  rect 1.143x1.448 smd: 1(-0.9,0) 2(0.9,0)
C1210-2
  rect 1.575x2.692 smd: 1(-1.397,0) 2(1.397,0)
C1210H110
  rect 1.372x2.794 smd: 1(-1.431,0) 2(1.431,0)
C3528
  rect 2.032x2.21 smd: N(1.524,0) P(-1.524,0)
CNMILLMAX2501
  round 3.048 hole 2.54: 1(0,0)
CNMOLEX87831-1420
  rect 1.422x1.422 hole 0.914: 1(0,0)
  round 1.422 hole 0.914: 2(0,2) 3(2,0) 4(2,2) 5(4,0) 6(4,2) 7(6,0) 8(6,2) 9(8,0) 10(8,2) 11(10,0) 12(10,2) 13(12,0) 14(12,2)
CNPEMKFH-032
  round 12.192 hole 4.851: 1(0,0)
CNSMASQ136H203
  round 0.889 smd: 1(0,0)
  rect 0.94x0.94 smd: 2(-1.32,-1.32) 3(1.32,-1.32) 4(1.32,1.32) 5(-1.32,1.32)
CNTHMHDR1X2L157W79H250
  rect 1.397x1.397 hole 0.889: 1(0,0)
  round 1.397 hole 0.889: 2(2,0)
CNTHMHDR1X3L236W79H244
  rect 1.397x1.397 hole 0.889: 1(0,0)
  round 1.397 hole 0.889: 2(2,0) 3(4,0)
CNTHMHDR1X4L315W79H250
  rect 1.397x1.397 hole 0.889: 1(0,0)
  round 1.397 hole 0.889: 2(2,0) 3(4,0) 4(6,0)
CNWURTH9774010243R
  round 3.302 hole 2.997 unplated: (0,0)
  round 0 smd: 1(0,0)
CPLRAD295D709H1240LD31
  round 1.651 hole 1.143: N(7.5,0)
  rect 1.651x1.651 hole 1.143: P(0,0)
CPLSMSQ327H461
  rect 3.81x2.032 smd: N(3.35,0) P(-3.35,0)
CPLSMSQ406H425
  rect 4.039x2.159 smd: N(4.2,0) P(-4.2,0)
DIE7_5X3
  rect 1.041x1.143 smd: 1(-2.414,1.222)
  rect 1.041x2.286 smd: 2(-2.414,-0.658)
  rect 0.457x3.607 smd: 3(-1.275,0) 4(-0.425,0) 5(0.425,0) 6(1.275,0)
  rect 1.041x3.607 smd: 7(2.414,0)
LSML528W591H512
  rect 2.972x11.201 smd: 1(-4.305,0) 2(4.305,0)
QFP64_10X10_PAD5_74X5_74_05-08-1982
  rect 0.254x1.295 smd: 1(-3.75,-5.75) 2(-3.25,-5.75) 3(-2.75,-5.75) 4(-2.25,-5.75) 5(-1.75,-5.75) 6(-1.25,-5.75) 7(-0.75,-5.75) 8(-0.25,-5.75) 9(0.25,-5.75) 10(0.75,-5.75) 11(1.25,-5.75) 12(1.75,-5.75) 13(2.25,-5.75) 14(2.75,-5.75) 15(3.25,-5.75) 16(3.75,-5.75) 33(3.75,5.75) 34(3.25,5.75) 35(2.75,5.75) 36(2.25,5.75) 37(1.75,5.75) 38(1.25,5.75) 39(0.75,5.75) 40(0.25,5.75) 41(-0.25,5.75) 42(-0.75,5.75) 43(-1.25,5.75) 44(-1.75,5.75) 45(-2.25,5.75) 46(-2.75,5.75) 47(-3.25,5.75) 48(-3.75,5.75)
  rect 1.295x0.254 smd: 17(5.75,-3.75) 18(5.75,-3.25) 19(5.75,-2.75) 20(5.75,-2.25) 21(5.75,-1.75) 22(5.75,-1.25) 23(5.75,-0.75) 24(5.75,-0.25) 25(5.75,0.25) 26(5.75,0.75) 27(5.75,1.25) 28(5.75,1.75) 29(5.75,2.25) 30(5.75,2.75) 31(5.75,3.25) 32(5.75,3.75) 49(-5.75,3.75) 50(-5.75,3.25) 51(-5.75,2.75) 52(-5.75,2.25) 53(-5.75,1.75) 54(-5.75,1.25) 55(-5.75,0.75) 56(-5.75,0.25) 57(-5.75,-0.25) 58(-5.75,-0.75) 59(-5.75,-1.25) 60(-5.75,-1.75) 61(-5.75,-2.25) 62(-5.75,-2.75) 63(-5.75,-3.25) 64(-5.75,-3.75)
  rect 5.74x5.74 smd: 65(0,0)
R0402
  rect 0.635x0.737 smd: 1(-0.5,0) 2(0.5,0)
R0603
  rect 0.787x0.991 smd: 1(-0.85,0) 2(0.85,0)
R0805
  rect 1.041x1.397 smd: 1(-0.95,0) 2(0.95,0)
R1225H28
  rect 0.991x6.579 smd: 1(-1.595,0) 2(1.595,0)
SOD323F_B
  rect 0.889x0.508 smd: A(1.3,0) C(-1.3,0)
SWTHL354W142H217
  rect 1.397x1.397 hole 0.889: 1(0,0)
  round 1.397 hole 0.889: 2(2.489,0) 3(4.978,0) 4(0,3.302) 5(2.489,3.302) 6(4.978,3.302)
TSSOP8
  rect 0.33x1.651 smd: 1(-0.975,-2.92) 2(-0.325,-2.92) 3(0.325,-2.92) 4(0.975,-2.92) 5(0.975,2.92) 6(0.325,2.92) 7(-0.325,2.92) 8(-0.975,2.92)
unnamed#2
  round 1.016 smd: (0,0)
WLCSP16_12P_1_67X1_67H0_56
  round 0.203 smd: A1(-0.6,0.6) A2(-0.2,0.6) A3(0.2,0.6) A4(0.6,0.6) B1(-0.6,0.2) B4(0.6,0.2) C1(-0.6,-0.2) C4(0.6,-0.2) D1(-0.6,-0.6) D2(-0.2,-0.6) D3(0.2,-0.6) D4(0.6,-0.6)

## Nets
3.3V_5V: C44.2(N2) J6.2 JP1.3(N3) R417.1
PGND: C1.2(N2) C2.2(N2) C3.2(N2) C4.1 C5.1 C6.1 C7.1 C8.1 C9.1 C10.2(N2) C11.1 C12.2(N2) C13.2(N2) C16.2(N2) C17.2(N2) C18.N(N2) C19.2(N2) C20.N(N2) C21.2(N2) C22.2(N2) C23.2(N2) C24.2(N2) C25.N(N2) C26.2(N2) C27.N(N2) C28.N(N2) C29.N(N2) C30.N(N2) C31.2(N2) C32.N(N2) C33.N(N2) C34.N(N2) C35.N(N2) C36.N(N2) C37.N(N2) C38.N(N2) C39.2(N2) C40.N(N2) C41.N(N2) C42.N(N2) C43.1 C44.1 C45.N(N2) C46.N(N2) C47.N(N2) C48.N(N2) C49.N(N2) C50.N(N2) C51.N(N2) C52.N(N2) C53.N(N2) C56.1 C65.2(N2) C66.2(N2) C148.2(N2) C168.N(N2) C169.2(N2) C189.2(N2) C194.2(N2) C195.2(N2) C196.2(N2) C197.2(N2) C700.2(N2) C702.1 C703.1 C704.1 C705.1 C708.2(N2) C709.2(N2) C710.2(N2) C713.1 C716.1 C717.2(N2) C718.2(N2) C720.1 C721.1 C722.1 C723.1 C724.1 C725.1 C730.2(N2) C731.2(N2) C732.2(N2) C733.2(N2) C734.2(N2) C739.2(N2) C740.2(N2) C741.2(N2) C744.2(N2) C745.2(N2) C746.2(N2) C747.2(N2) C750.1 C751.2(N2) C752.2(N2) C754.1 C755.1 C757.1 C758.1 C759.1 C764.2(N2) C765.2(N2) C766.2(N2) C767.2(N2) C768.2(N2) C773.2(N2) C774.2(N2) C775.2(N2) C777.2(N2) C778.2(N2) C779.2(N2) C780.2(N2) C800.1 C801.2(N2) C802.2(N2) C804.1 C805.1 C806.1 C807.1 C808.1 C809.1 C814.2(N2) C815.2(N2) C816.2(N2) C817.2(N2) C818.2(N2) C823.2(N2) C824.2(N2) C825.2(N2) C828.2(N2) C829.2(N2) C830.2(N2) C831.2(N2) C834.1 C835.2(N2) C836.2(N2) C838.1 C839.1 C840.1 C841.1 C842.1 C843.1 C848.2(N2) C849.2(N2) C850.2(N2) C851.2(N2) C852.2(N2) C857.2(N2) C858.2(N2) C859.2(N2) C862.2(N2) C863.2(N2) C864.2(N2) C865.2(N2) C868.1 C869.2(N2) C870.2(N2) C873.1 C874.1 C875.1 C876.1 C877.1 C878.1 C883.2(N2) C884.2(N2) C885.2(N2) C886.2(N2) C887.2(N2) C892.2(N2) C893.2(N2) C894.2(N2) C897.2(N2) C898.2(N2) C899.2(N2) C900.2(N2) D13.A(P) E14.1(N1) E15.1(N1) E20.1(N1) E25.1(N1) E40.1(N1) J2.1(N1) J5.1(N1) J6.3 J6.8 J6.12 J6.13 J9.1(N1) J11.1(N1) J13.1(N1) JP3.4(N4) JP4.3(N3) JP21.2 P1.2(N2) P2.1 P3.2(N2) P4.1 P5.2(N2) P6.1 P7.2(N2) P8.1 P9.2(N2) P10.1 P11.2(N2) P12.1 Q2.2 Q2.4 Q2.6(S3) Q4.2 Q4.4 Q4.6(S3) Q6.2 Q6.4 Q6.6(S3) Q8.2 Q8.4 Q8.6(S3) Q10.2 Q10.4 Q10.6(S3) Q12.2 Q12.4 Q12.6(S3) R8.1 R9.1 R17.2(N2) R20.2(N2) R36.1 R44.1 R425.2(N2) R428.2(N2) R430.2(N2) R438.2(N2) R457.1 R466.2(N2) R468.2(N2) R701.1 R705.2(N2) R712.1 R714.2(N2) R723.1 R725.2(N2) R802.1 R804.2(N2) R814.1 R816.2(N2) R825.1 R827.2(N2) S1.6(NO2) U1.A2 U2.A2 U3.A2 U4.A2 U5.A2 U6.A2 U7.5 U7.16 U7.45 U7.65 U8.1 U8.2 U8.3 U8.4
V5: C10.1 C43.2(N2) C700.1 JP1.2 JP3.1 R5.1 R6.2(N2) R7.1 R13.2(N2) R18.1 R123.1 R418.1 R456.1 U7.9
_N1: C9.2(N2) U7.1
_N2: C5.2(N2) R10.2(N2) U7.4
_N4: C6.2(N2) R10.1
_N5: R7.2(N2) R17.1 U7.49
_N7: C11.2(N2) R11.2(N2) U7.6
_N8: C7.2(N2) R11.1
_N9: C196.1 R2.2(N2) R8.2(N2) U7.14
_N20: C189.1 R1.1 R36.2(N2) U7.13
_N24: C39.1 R29.2(N2) U7.48(VHIGH)
_N30: C2.1 C168.P D12.C D13.C E1.1(N1) R414.2(N2) U7.42
_N31: C166.2(N2) R427.2(N2) R428.1 U7.3
_N32: C166.1 R426.2(N2) R427.1
_N45: C167.2(N2) C195.1 R430.1 R431.2(N2) U7.7
_N47: C167.1 R429.2(N2) R431.1
_N68: R20.1 U7.44
_N69: E9.1(N1) R18.2(N2) U7.35
_N73: JP3.2 JP3.3 U7.51
_N75: R44.2(N2) U7.53
_N76: E21.1(N1) R456.2(N2) R457.2(N2) U7.52
_N78: E3.1(N1) U7.50
_N79: R9.2(N2) R15.2(N2) U7.15
_N81: C12.1 E2.1(N1) U7.10
_N86: C148.1 E5.1(N1) S1.2 U7.11
_N95: C197.1 P28.1 R464.2(N2) R468.1
_N100: J6.4 R415.1
_N101: J6.6 R416.1
_N102: J6.7 R12.1
_N108: J6.11 R439.2(N2) U8.6
_N109: C169.1 J6.10 R439.1 R440.1 R441.1 U8.8
_N111: J6.9(N9) R441.2(N2) U8.5
_N113: JP21.1 R440.2(N2) U8.7(WP)
_N115: R701.2(N2) R702.2(N2) U1.A4
_N120: C4.2(N2) R703.2(N2) U1.B4
_N122: R704.2(N2) R705.1 U1.C4
_N123: C701.1 U1.D3
_N125: R4.1 U1.B1
_N126: R3.1 U1.D2
_N129: C701.2(N2) J15.2 J15.3 J15.4 J15.5(SH4) L1.1 P2.2(N2) Q1.2 Q1.4 Q1.6(S3) Q2.3 Q2.5 Q2.7 R706.1 U1.C1 U1.D4
_N137: L1.2(N2) R708.1 R709.1
_N157: R711.2(N2) R712.2(N2) U2.A4
_N158: C716.2(N2) R710.2(N2) U2.B4
_N159: R713.2(N2) R714.1 U2.C4
_N160: C719.1 U2.D3
_N161: R716.1 U2.B1
_N162: R715.1 U2.D2
_N163: C719.2(N2) J17.2 J17.3 J17.4 J17.5(SH4) L2.1 P4.2(N2) Q3.2 Q3.4 Q3.6(S3) Q4.3 Q4.5 Q4.7 R717.1 U2.C1 U2.D4
_N164: L2.2(N2) R719.1 R720.1
_N189: R722.2(N2) R723.2(N2) U3.A4
_N190: C750.2(N2) R721.2(N2) U3.B4
_N191: R724.2(N2) R725.1 U3.C4
_N192: C753.1 U3.D3
_N193: R727.1 U3.B1
_N194: R726.1 U3.D2
_N195: C753.2(N2) J3.2 J3.3 J3.4 J3.5(SH4) L3.1 P6.2(N2) Q5.2 Q5.4 Q5.6(S3) Q6.3 Q6.5 Q6.7 R728.1 U3.C1 U3.D4
_N196: L3.2(N2) R729.1 R731.1
_N205: R801.2(N2) R802.2(N2) U4.A4
_N206: C800.2(N2) R800.2(N2) U4.B4
_N207: R803.2(N2) R804.1 U4.C4
_N208: C803.1 U4.D3
_N209: R806.1 U4.B1
_N210: R805.1 U4.D2
_N211: C803.2(N2) J4.2 J4.3 J4.4 J4.5(SH4) L4.1 P8.2(N2) Q7.2 Q7.4 Q7.6(S3) Q8.3 Q8.5 Q8.7 R807.1 U4.C1 U4.D4
_N212: L4.2(N2) R809.1 R811.1
_N213: R813.2(N2) R814.2(N2) U5.A4
_N214: C834.2(N2) R812.2(N2) U5.B4
_N215: R815.2(N2) R816.1 U5.C4
_N216: C837.1 U5.D3
_N217: R818.1 U5.B1
_N218: R817.1 U5.D2
_N219: C837.2(N2) J16.2 J16.3 J16.4 J16.5(SH4) L5.1 P10.2(N2) Q9.2 Q9.4 Q9.6(S3) Q10.3 Q10.5 Q10.7 R819.1 U5.C1 U5.D4
_N220: L5.2(N2) R820.1 R821.1
_N221: R824.2(N2) R825.2(N2) U6.A4
_N222: C868.2(N2) R823.2(N2) U6.B4
_N223: R826.2(N2) R827.1 U6.C4
_N224: C871.1 U6.D3
_N225: R829.1 U6.B1
_N226: R828.1 U6.D2
_N227: C871.2(N2) J14.2 J14.3 J14.4 J14.5(SH4) L6.1 P12.2(N2) Q11.2 Q11.4 Q11.6(S3) Q12.3 Q12.5 Q12.7 R830.1 U6.C1 U6.D4
_N228: L6.2(N2) R831.1 R832.1
_N265: R6.1 R425.1 S1.1
_N266: R13.1 R438.1 S1.3
_N267: R5.2(N2) S1.4
_N375: J15.1 Q1.1 R3.2(N2) U1.D1
_N376: P1.1 Q2.1 R4.2(N2) U1.A1
_N377: J17.1 Q3.1 R715.2(N2) U2.D1
_N378: P3.1 Q4.1 R716.2(N2) U2.A1
_N379: J3.1 Q5.1 R726.2(N2) U3.D1
_N380: P5.1 Q6.1 R727.2(N2) U3.A1
_N381: J4.1 Q7.1 R805.2(N2) U4.D1
_N382: P7.1 Q8.1 R806.2(N2) U4.A1
_N383: J16.1 Q9.1 R817.2(N2) U5.D1
_N384: P9.1 Q10.1 R818.2(N2) U5.A1
_N385: J14.1 Q11.1 R828.2(N2) U6.D1
_N386: P11.1 Q12.1 R829.2(N2) U6.A1
_N505: C194.1 P28.4(N4) R465.2(N2) R466.1
BUCK: E4.1(N1) S1.5 U7.54
CSB: E31.1(N1) R416.2(N2) U7.37
DRVCC: C1.1 C3.1 C31.1 C717.1 C718.1 C751.1 C752.1 C801.1 C802.1 C835.1 C836.1 C869.1 C870.1 R702.1 R711.1 R722.1 R801.1 R813.1 R824.1 U1.A3(VCC) U2.A3(VCC) U3.A3(VCC) U4.A3(VCC) U5.A3(VCC) U6.A3(VCC) U7.46
PGOOD: E33.1(N1) R123.2(N2) U7.30
PWM1: R703.1 U7.29
PWM2: R710.1 U7.31
PWM3: R721.1 U7.32
PWM4: R800.1 U7.33
PWM5: R812.1 U7.34
PWM6: R823.1 U7.36
PWMEN: E22.1(N1) R418.2(N2) R704.1 R713.1 R724.1 R803.1 R815.1 R826.1 U7.28
RUN: E34.1(N1) JP4.2 P28.2 P28.3 U7.27
SAC1: C715.1 R458.1 R706.2(N2) R707.1 U7.17
SAC2: C742.1 R459.1 R717.2(N2) R718.1 U7.22
SAC3: C776.1 R460.1 R728.2(N2) R730.1 U7.23
SAC4: C826.1 R461.1 R807.2(N2) R810.1 U7.58
SAC5: C860.1 R462.1 R819.2(N2) R822.1 U7.59
SAC6: C896.1 R463.1 R830.2(N2) R833.1 U7.64
SCL: E29.1(N1) R415.2(N2) U7.40
SDA: E32.1(N1) R12.2(N2) U7.39
SDC1: C14.1 R458.2(N2) R708.2(N2) U7.19
SDC2: C743.1 R459.2(N2) R719.2(N2) U7.20
SDC3: C783.1 R460.2(N2) R729.2(N2) U7.25
SDC4: C827.1 R461.2(N2) R809.2(N2) U7.56
SDC5: C861.1 R462.2(N2) R820.2(N2) U7.61
SDC6: C895.1 R463.2(N2) R831.2(N2) U7.62
SDO: E30.1(N1) J6.5 R417.2(N2) U7.38
SN1: C14.2(N2) C17.1 C18.P C19.1 C20.P C21.1 C23.1 C25.P C27.P C28.P C29.P C30.P C32.P C33.P C34.P C35.P C36.P C37.P C38.P C65.1 C715.2(N2) C742.2(N2) C743.2(N2) C744.1 C745.1 C746.1 C747.1 C776.2(N2) C777.1 C778.1 C779.1 C780.1 C783.2(N2) C826.2(N2) C827.2(N2) C828.1 C829.1 C830.1 C831.1 C860.2(N2) C861.2(N2) C862.1 C863.1 C864.1 C865.1 C895.2(N2) C896.2(N2) C897.1 C898.1 C899.1 C900.1 D12.A(P) E19.1(N1) J7.1(N1) J8.1(N1) J10.1(N1) R15.1 R414.1 R426.1 R465.1 R707.2(N2) R709.2(N2) R718.2(N2) R720.2(N2) R730.2(N2) R731.2(N2) R810.2(N2) R811.2(N2) R821.2(N2) R822.2(N2) R832.2(N2) R833.2(N2) U7.18 U7.21 U7.24 U7.57 U7.60 U7.63
VHIGH: C8.2(N2) C13.1 C16.1 C22.1 C24.1 C26.1 C40.P C41.P C42.P C45.P C46.P C47.P C48.P C49.P C50.P C51.P C52.P C53.P C56.2(N2) C66.1 C702.2(N2) C703.2(N2) C704.2(N2) C705.2(N2) C708.1 C709.1 C710.1 C713.2(N2) C720.2(N2) C721.2(N2) C722.2(N2) C723.2(N2) C724.2(N2) C725.2(N2) C730.1 C731.1 C732.1 C733.1 C734.1 C739.1 C740.1 C741.1 C754.2(N2) C755.2(N2) C757.2(N2) C758.2(N2) C759.2(N2) C764.1 C765.1 C766.1 C767.1 C768.1 C773.1 C774.1 C775.1 C804.2(N2) C805.2(N2) C806.2(N2) C807.2(N2) C808.2(N2) C809.2(N2) C814.1 C815.1 C816.1 C817.1 C818.1 C823.1 C824.1 C825.1 C838.2(N2) C839.2(N2) C840.2(N2) C841.2(N2) C842.2(N2) C843.2(N2) C848.1 C849.1 C850.1 C851.1 C852.1 C857.1 C858.1 C859.1 C873.2(N2) C874.2(N2) C875.2(N2) C876.2(N2) C877.2(N2) C878.2(N2) C883.1 C884.1 C885.1 C886.1 C887.1 C892.1 C893.1 C894.1 E11.1(N1) J1.1(N1) J12.1(N1) Q1.3 Q1.5 Q1.7 Q3.3 Q3.5 Q3.7 Q5.3 Q5.5 Q5.7 Q7.3 Q7.5 Q7.7 Q9.3 Q9.5 Q9.7 Q11.3 Q11.5 Q11.7 R1.2(N2) R2.1 R29.1 R429.1 R464.1

Pads without a net: J6 1 14; JP1 1; JP4 1; JP21 3; P16 1; P17 1; P18 1; P19 1; P20 1; P21 1; P22 1; P23 1; P24 1; P25 1; P26 1; P27 1; U7 2 8 12 26 41 43 47 55

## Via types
v1: diameter 0.508, hole 0.254, TOP to BOTTOM, 490 vias
v2: diameter 0.508, hole 0.305, TOP to BOTTOM, 2807 vias
v3: diameter 0.305, hole 0.152, TOP to BOTTOM, 1368 vias

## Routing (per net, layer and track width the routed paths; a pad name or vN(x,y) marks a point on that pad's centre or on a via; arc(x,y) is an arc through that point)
3.3V_5V: length 29.4
  TOP w0.381: JP1.3 27.95,19.89 27.99,19.86 C44.2
  L7_SIG w0.381: J6.2 6.37,19.32 6.37,19 7.32,18.05 17.99,18.05 19.83,19.89 JP1.3
  BOTTOM w0.254: R417.1 7.13,17.44 5.73,18.84 J6.2
PGND: length 94.2
  TOP w0.203: 193.02,82.34 U6.A2 ; 193.02,82.34 193,82.34 ; 193.02,82.34 192.83,82.15 v1(192.81,82.15) ; v1(63.78,82.15) 63.78,82.15 63.97,82.34 64.17,82.34 64.18,82.34 U2.A2 ; 164.24,82.34 164.05,82.34 v1(163.86,82.15) 164.05,82.34 U5.A2 ; 128.5,82.34 128.31,82.15 v1(128.3,82.15) ; 128.5,82.34 U4.A2 ; 128.5,82.34 128.49,82.34 ; U1.A2 35.02,82.34 v1(34.83,82.15) ; 99.54,82.34 99.54,82.34 v1(99.35,82.15) 99.54,82.34 ; 99.54,82.34 U3.A2
  TOP w0.305: v1(32.2,19.85) 32.2,19.86 C44.1 ; C43.1 v1(32.35,21.87)
  L2_PWR w0.305: v3(35.05,74.43) v3(35.55,74.43) ; v3(35.05,75.95) v3(35.55,75.95) ; v3(35.05,71.38) v3(35.55,71.38) ; v3(35.55,77.48) v3(35.05,77.48) ; v3(35.55,72.92) v3(35.05,72.92)
  L3_PWR w0.305: v3(35.05,71.38) v3(35.55,71.38)
  L4_PWR w0.305: v3(35.05,71.38) v3(35.55,71.38)
  L6_SIG w0.203: 222.94,20.54 S1.6 ; S1.6 224.1,19.38 ; S1.6 224.1,20.54 ; S1.6 222.94,19.38
  L7_SIG w0.305: 181.6,64.36 181.6,64.36
  L7_SIG w0.508: E25.1 3.34,104.55 3.34,42.76 E15.1
  BOTTOM w0.203: C26.2 51.83,97.16 51.37,97.62 ; C740.2 83.65,91.9 83.65,90.99 v3(83.88,91.22) ; C823.2 v3(148.49,92.13) 148.92,91.7 149.2,91.7 149.45,91.95
  BOTTOM w0.508: R425.2 v1(217.3,26.64) ; C169.2 13.54,35.03 ; R438.2 v1(217.3,18.26)
  vias: v1(14.96,37.23) v1(15.61,37.23) v1(16.26,37.23) v1(16.91,37.23) v1(27.28,79.93) v1(27.28,78.18) v1(27.28,76.42) v1(27.28,74.67) v1(27.71,80.84) v1(27.71,79.08) v1(27.71,77.33) v1(27.71,75.57) v1(28.04,79.93) v1(28.04,78.18) v1(28.04,76.42) v1(28.04,74.67) v1(28.47,80.84) v1(28.47,79.08) v1(28.47,77.33) v1(28.47,75.57) v1(28.81,79.93) v1(28.81,78.18) v1(28.81,76.42) v1(28.81,74.67) v1(29.24,80.84) v1(29.24,79.08) v1(29.24,77.33) v1(29.24,75.57) v1(29.57,79.93) v1(30,80.84) v1(33.62,81.52) v1(41.36,22.75) v1(41.35,21.24) v1(41.38,19.72) v1(42.5,19.76) v1(42.57,22.7) v1(42.55,21.24) v1(51.87,22.7) v1(51.86,21.19) v1(51.89,19.67) v1(53.01,19.71) v1(53.08,22.65) v1(53.06,21.19) v1(56.23,79.93) v1(56.23,78.18) v1(56.23,76.42) v1(56.23,74.67) v1(56.66,80.84) v1(56.66,79.08) v1(56.66,77.33) v1(56.66,75.57) v1(57,79.93) v1(57,78.18) v1(57,76.42) v1(57,74.67) v1(57.42,80.84) v1(57.42,79.08) v1(57.42,77.33) v1(57.42,75.57) v1(57.76,79.93) v1(57.76,78.18) v1(57.76,76.42) v1(57.76,74.67) v1(58.19,80.84) v1(58.19,79.08) v1(58.19,77.33) v1(58.19,75.57) v1(58.52,79.93) v1(58.95,80.84) v1(62.59,22.88) v1(62.58,21.37) v1(62.61,19.85) v1(62.75,81.52) v1(63.73,19.89) v1(63.8,22.83) v1(63.79,21.37) v1(73.05,22.93) v1(73.04,21.42) v1(73.08,19.9) v1(74.19,19.94) v1(74.26,22.88) v1(74.25,21.42) v1(83.42,22.89) v1(83.41,21.38) v1(83.44,19.87) v1(84.63,22.85) v1(84.61,21.38) v1(84.56,19.91) v1(91.8,79.93) v1(91.8,78.18) v1(91.8,76.42) v1(91.8,74.67) v1(92.23,80.84) v1(92.23,79.08) v1(92.23,77.33) v1(92.23,75.57) v1(92.56,79.93) v1(92.56,78.18) v1(92.56,76.42) v1(92.56,74.67) v1(92.99,80.84) v1(92.99,79.08) v1(92.99,77.33) v1(92.99,75.57) v1(93.32,79.93) v1(93.32,78.18) v1(93.32,76.42) v1(93.32,74.67) v1(93.38,23.07) v1(93.37,21.56) v1(93.4,20.05) v1(93.75,80.84) v1(93.75,79.08) v1(93.75,77.33) v1(93.75,75.57) v1(94.08,79.93) v1(94.51,80.84) v1(94.52,20.09) v1(94.59,23.03) v1(94.57,21.56) v1(98.32,81.52) v1(101.87,32.21) v1(104.83,39.32) v1(106.77,27.28) v1(108.19,27.28) v1(109.57,26.52) v1(110.68,26.52) v1(112.01,40.63) v1(112.01,39.1) v1(112.01,37.58) v1(112.01,36.06) v1(113.54,40.63) v1(113.54,39.1) v1(113.54,37.58) v1(113.54,36.06) v1(114.3,54.01) v1(114.3,22.45) v1(115.06,40.63) v1(115.06,39.1) v1(115.06,37.58) v1(115.06,36.06) v1(116.59,40.63) v1(116.59,39.1) v1(116.59,37.58) v1(116.59,36.06) v1(120.75,79.93) v1(120.75,76.42) v1(120.75,74.67) v1(121.18,80.84) v1(121.18,79.08) v1(121.18,77.33) v1(121.18,75.57) v1(121.51,79.93) v1(121.51,78.18) v1(121.51,76.42) v1(121.51,74.67) v1(121.94,80.84) v1(121.94,79.08) v1(121.94,77.33) v1(121.94,75.57) v1(122.27,79.93) v1(122.27,78.18) v1(122.27,76.42) v1(122.27,74.67) v1(122.32,51.63) v1(122.7,80.84) v1(122.7,79.08) v1(122.7,77.33) v1(122.7,75.57) v1(123.04,79.93) v1(123.46,80.84) v1(127.27,81.52) v1(142.59,22.62) v1(142.58,21.11) v1(142.61,19.59) v1(143.73,19.63) v1(143.8,22.57) v1(143.79,21.11) v1(152.52,22.67) v1(152.51,21.16) v1(152.54,19.64) v1(153.73,22.62) v1(153.71,21.16) v1(153.65,19.68) v1(156.31,79.93) v1(156.31,78.18) v1(156.31,76.42) v1(156.31,74.67) v1(156.74,80.84) v1(156.74,79.08) v1(156.74,77.33) v1(156.74,75.57) v1(157.08,79.93) v1(157.08,78.18) v1(157.08,76.42) v1(157.08,74.67) v1(157.51,80.84) v1(157.51,79.08) v1(157.51,77.33) v1(157.51,75.57) v1(157.84,79.93) v1(157.84,78.18) v1(157.84,76.42) v1(157.84,74.67) v1(158.27,80.84) v1(158.27,79.08) v1(158.27,77.33) v1(158.27,75.57) v1(158.6,79.93) v1(159.03,80.84) v1(162.53,20.94) v1(162.54,22.45) v1(162.56,19.43) v1(162.83,81.52) v1(163.73,20.94) v1(163.68,19.47) v1(163.75,22.41) v1(172.25,22.37) v1(172.24,20.86) v1(172.27,19.35) v1(173.39,19.39) v1(173.46,22.33) v1(173.44,20.86) v1(181.98,22.65) v1(181.97,21.14) v1(182,19.62) v1(183.12,19.66) v1(183.19,22.6) v1(183.17,21.14) v1(185.27,79.93) v1(185.27,78.18) v1(185.27,76.42) v1(185.27,74.67) v1(185.69,80.84) v1(185.69,79.08) v1(185.69,77.33) v1(185.69,75.57) v1(186.03,79.93) v1(186.03,78.18) v1(186.03,76.42) v1(186.03,74.67) v1(186.46,80.84) v1(186.46,79.08) v1(186.46,77.33) v1(186.46,75.57) v1(186.79,79.93) v1(186.79,78.18) v1(186.79,76.42) v1(186.79,74.67) v1(187.22,80.84) v1(187.22,79.08) v1(187.22,77.33) v1(187.22,75.57) v1(187.55,79.93) v1(187.98,80.84) v1(191.59,22.71) v1(191.58,21.21) v1(191.61,19.69) v1(191.78,81.52) v1(192.73,19.73) v1(192.8,22.67) v1(192.78,21.21) v2(5.53,58.83) v2(5.59,122.43) v2(5.59,117.35) v2(5.59,112.27) v2(5.59,102.11) v2(5.59,97.03) v2(5.59,86.87) v2(5.59,81.79) v2(5.59,71.63) v2(5.59,66.55) v2(5.59,51.31) v2(5.59,10.67) v2(8.26,81.58) v2(10.5,69.1) v2(10.5,64.05) v2(10.5,48.83) v2(10.62,125.03) v2(10.62,114.85) v2(10.62,109.58) v2(10.58,104.41) v2(10.58,94.52) v2(10.61,58.83) v2(10.67,137.67) v2(10.67,135.26) v2(10.67,132.59) v2(10.67,130) v2(10.67,127.51) v2(10.67,122.43) v2(10.71,119.98) v2(10.67,117.35) v2(10.67,112.27) v2(10.67,107.19) v2(10.67,102.11) v2(10.67,91.95) v2(10.67,86.87) v2(10.67,76.71) v2(10.67,71.63) v2(10.67,66.55) v2(10.67,61.47) v2(10.67,56.39) v2(10.67,53.8) v2(10.67,51.31) v2(10.67,46.23) v2(10.71,43.4) v2(10.67,5.59) v2(10.75,99.66) v2(11.71,83.48) v2(13.27,74.67) v2(14.43,7.77) v2(14.43,3.49) v2(15.58,48.83) v2(15.7,125.03) v2(15.7,114.85) v2(15.7,109.58) v2(15.66,104.41) v2(15.66,94.52) v2(15.69,58.83) v2(15.75,137.67) v2(15.75,135.26) v2(15.75,132.59) v2(15.75,130) v2(15.75,127.51) v2(15.75,122.43) v2(15.79,119.98) v2(15.75,117.35) v2(15.75,112.27) v2(15.75,107.19) v2(15.75,102.11) v2(15.83,99.66) v2(15.75,97.03) v2(15.75,86.87) v2(15.75,81.79) v2(15.75,71.63) v2(15.75,66.55) v2(15.77,64.14) v2(15.75,61.47) v2(15.75,56.39) v2(15.75,53.8) v2(15.75,51.31) v2(15.75,46.23) v2(15.79,43.4) v2(16.98,77.95) v2(18.14,7.85) v2(18.14,3.49) v2(18.23,84.56) v2(20.66,48.83) v2(20.83,137.67) v2(20.83,135.26) v2(20.83,132.59) v2(20.83,130) v2(20.83,127.51) v2(20.78,125.03) v2(20.83,122.43) v2(20.83,117.35) v2(20.78,114.85) v2(20.83,112.27) v2(20.78,109.58) v2(20.83,107.19) v2(20.74,104.41) v2(20.83,102.11) v2(20.83,97.03) v2(20.74,94.52) v2(20.83,91.95) v2(20.83,81.79) v2(20.83,76.71) v2(20.83,71.63) v2(20.83,66.55) v2(20.83,61.47) v2(20.77,58.83) v2(20.83,56.39) v2(20.83,53.8) v2(20.83,51.31) v2(20.83,46.23) v2(20.83,41.15) v2(20.83,36.07) v2(20.83,30.99) v2(20.87,119.98) v2(20.91,99.66) v2(20.87,43.4) v2(23.06,36.17) v2(23.32,79.55) v2(25.6,31.12) v2(25.7,51.23) v2(25.74,48.83) v2(25.82,104.41) v2(25.82,94.52) v2(25.91,137.67) v2(25.91,135.26) v2(25.91,132.59) v2(25.91,130) v2(25.91,127.51) v2(25.86,125.03) v2(25.91,122.43) v2(25.91,117.35) v2(25.86,114.85) v2(25.91,112.27) v2(25.86,109.58) v2(25.91,107.19) v2(25.91,102.11) v2(25.91,97.03) v2(25.91,91.95) v2(25.91,76.71) v2(25.91,61.47) v2(25.85,58.83) v2(25.91,56.39) v2(25.91,53.8) v2(25.86,46.44) v2(25.91,36.07) v2(25.95,119.98) v2(25.99,99.66) v2(25.95,43.4) v2(25.96,40.66) v2(28.79,49.29) v2(28.79,44.21) v2(30.42,35.45) v2(30.42,30.37) v2(30.9,104.41) v2(30.9,94.52) v2(30.99,137.67) v2(30.99,135.26) v2(30.99,132.59) v2(30.99,130) v2(30.99,127.51) v2(30.94,125.03) v2(30.99,122.43) v2(31.03,119.98) v2(30.99,117.35) v2(30.94,114.85) v2(30.94,109.58) v2(30.99,107.19) v2(30.99,97.03) v2(30.99,91.95) v2(31.07,99.66) v2(33.87,49.29) v2(33.87,44.21) v2(35.5,35.45) v2(35.5,30.37) v2(35.85,21.62) v2(40.92,120.56) v2(40.92,115.48) v2(41.99,37.27) v2(41.99,32.19) v2(45.27,52.18) v2(45.27,50.91) v2(45.27,49.64) v2(45.27,48.37) v2(45.27,47.1) v2(45.27,45.83) v2(45.31,44.61) v2(45.31,43.34) v2(45.31,42.07) v2(45.31,40.8) v2(45.32,39.7) v2(46,120.56) v2(46,115.48) v2(46.54,52.18) v2(46.54,50.91) v2(46.54,49.64) v2(46.54,48.37) v2(46.54,47.1) v2(46.54,45.83) v2(46.58,44.61) v2(46.58,43.34) v2(46.58,42.07) v2(46.54,40.95) v2(46.54,39.68) v2(47.07,37.27) v2(47.07,32.19) v2(49.45,41.96) v2(49.45,40.18) v2(49.45,38.4) v2(49.45,35.1) v2(49.45,33.32) v2(51,41.96) v2(51,40.18) v2(51,38.4) v2(51,35.1) v2(51,33.32) v2(51.26,61) v2(51.29,59.79) v2(51.29,58.52) v2(51.29,57.25) v2(51.29,55.98) v2(51.29,54.71) v2(51.29,53.44) v2(51.26,52.18) v2(51.26,50.91) v2(51.26,49.64) v2(51.41,81.75) v2(51.49,79.65) v2(51.58,78.44) v2(51.61,73.27) v2(51.66,77.08) v2(51.66,75.84) v2(51.69,74.54) v2(51.69,72.05) v2(51.7,66.89) v2(51.82,103.9) v2(51.78,102.37) v2(51.78,101.1) v2(51.74,99.78) v2(51.74,98.51) v2(51.78,70.69) v2(51.78,69.45) v2(51.81,68.15) v2(51.76,65.7) v2(52.42,60.95) v2(52.42,52.13) v2(52.42,50.86) v2(52.42,49.59) v2(52.45,59.73) v2(52.45,58.46) v2(52.45,57.19) v2(52.45,55.92) v2(52.45,54.65) v2(52.45,53.38) v2(53.04,99.78) v2(53.04,98.51) v2(53,97.25) v2(53.03,96.12) v2(53.02,93.67) v2(53.02,92.4) v2(53.11,103.9) v2(53.08,102.37) v2(53.08,101.1) v2(53.06,94.99) v2(53.09,81.79) v2(53.12,79.72) v2(53.09,77.12) v2(53.09,75.89) v2(53.12,74.57) v2(53.12,42.49) v2(53.17,78.54) v2(53.23,73.33) v2(53.2,70.74) v2(53.2,69.5) v2(53.23,68.18) v2(53.19,65.63) v2(53.29,72.15) v2(53.26,66.89) v2(53.42,37.37) v2(53.42,32.29) v2(53.73,121.58) v2(53.73,120.31) v2(53.73,118.7) v2(53.69,60.95) v2(53.72,59.73) v2(53.72,58.46) v2(53.72,57.19) v2(53.72,55.92) v2(53.72,54.65) v2(53.72,53.38) v2(53.69,52.13) v2(53.69,50.86) v2(53.69,49.59) v2(53.69,48.32) v2(54.23,94.89) v2(54.19,93.57) v2(54.19,92.3) v2(54.43,102.39) v2(54.43,101.12) v2(54.39,99.8) v2(54.39,98.53) v2(54.35,97.26) v2(54.35,96.1) v2(54.46,103.92) v2(54.67,79.72) v2(54.73,78.54) v2(54.69,77.14) v2(54.67,75.85) v2(54.73,74.58) v2(54.72,72.08) v2(54.8,81.76) v2(54.78,73.33) v2(54.8,70.75) v2(54.79,69.46) v2(54.84,68.2) v2(54.9,66.86) v2(54.91,65.69) v2(54.97,121.6) v2(54.97,120.33) v2(54.99,118.63) v2(54.94,60.92) v2(54.97,59.7) v2(54.97,58.43) v2(54.97,57.16) v2(54.97,55.89) v2(54.97,54.62) v2(54.97,53.35) v2(54.97,52.18) v2(54.97,50.91) v2(54.97,49.64) v2(54.97,48.37) v2(54.97,47.1) v2(54.97,45.83) v2(55.92,94.91) v2(55.88,93.59) v2(55.88,92.32) v2(56,73.28) v2(56.12,102.41) v2(56.12,101.14) v2(56.08,99.82) v2(56.08,98.55) v2(56.04,97.28) v2(56.04,96.12) v2(56.06,72.09) v2(56.15,103.94) v2(56.16,70.69) v2(56.14,69.41) v2(56.2,68.14) v2(56.21,60.92) v2(56.24,59.7) v2(56.24,58.43) v2(56.24,57.16) v2(56.24,55.89) v2(56.24,54.62) v2(56.24,53.35) v2(56.24,52.18) v2(56.24,50.91) v2(56.24,49.64) v2(56.24,48.37) v2(56.24,47.1) v2(56.24,45.83) v2(56.39,81.79) v2(57.49,72.02) v2(57.55,73.28) v2(57.7,94.91) v2(57.66,93.59) v2(57.66,92.32) v2(57.82,97.28) v2(57.82,96.12) v2(57.93,103.94) v2(57.9,102.41) v2(57.9,101.14) v2(57.86,99.82) v2(57.86,98.55) v2(58.2,40.89) v2(58.5,37.37) v2(58.5,32.29) v2(59.43,93.59) v2(59.43,92.32) v2(59.48,96.12) v2(59.48,94.91) v2(59.63,99.82) v2(59.63,98.55) v2(59.6,97.28) v2(59.71,103.94) v2(59.68,102.41) v2(59.68,101.14) v2(61.13,93.59) v2(61.13,92.32) v2(61.18,94.91) v2(61.33,99.82) v2(61.33,98.55) v2(61.3,97.28) v2(61.3,96.12) v2(61.41,103.94) v2(61.38,102.41) v2(61.38,101.14) v2(62.83,93.59) v2(62.83,92.32) v2(62.87,94.91) v2(63.03,99.82) v2(63.03,98.55) v2(63,97.28) v2(62.99,96.15) v2(62.97,40.99) v2(63.11,103.94) v2(63.07,102.41) v2(63.07,101.14) v2(63.27,37.47) v2(63.27,32.39) v2(64.33,99.82) v2(64.41,103.94) v2(64.37,102.41) v2(64.37,101.14) v2(64.38,98.57) v2(64.38,97.3) v2(65.99,121.55) v2(65.99,120.28) v2(65.99,118.67) v2(67.24,121.57) v2(67.24,120.3) v2(67.25,118.59) v2(68.49,40.97) v2(68.68,37.47) v2(68.68,32.39) v2(69.68,119.08) v2(69.68,114) v2(73.57,40.97) v2(73.76,39.37) v2(73.76,37.47) v2(74.21,53.34) v2(74.22,52.18) v2(74.22,50.91) v2(74.22,49.64) v2(74.22,48.37) v2(74.22,47.1) v2(74.22,45.83) v2(74.76,119.08) v2(74.76,114) v2(75.49,52.18) v2(75.49,50.91) v2(75.49,49.64) v2(75.49,48.37) v2(75.49,47.1) v2(75.49,45.83) v2(75.52,32.34) v2(76.01,40.89) v2(76.2,39.3) v2(76.2,37.4) v2(76.92,53.51) v2(76.9,50.91) v2(76.9,49.64) v2(76.9,48.37) v2(76.9,47.1) v2(76.9,45.83) v2(78.08,53.51) v2(78.05,52.38) v2(78.05,49.58) v2(78.11,48.36) v2(78.11,47.12) v2(78.08,45.82) v2(78.15,121.85) v2(78.15,120.58) v2(78.15,118.97) v2(78.34,41.07) v2(78.53,39.47) v2(78.53,37.57) v2(78.53,32.49) v2(79.39,121.87) v2(79.39,120.6) v2(79.41,118.89) v2(80.4,63.36) v2(80.42,62.13) v2(80.45,61) v2(80.58,69.48) v2(80.64,68.13) v2(80.69,66.74) v2(80.69,65.44) v2(80.88,40.94) v2(81.08,39.34) v2(81.08,37.44) v2(81.63,63.39) v2(81.67,62.16) v2(81.74,60.89) v2(81.77,59.76) v2(81.78,58.64) v2(81.82,57.08) v2(81.79,46.23) v2(81.85,56.06) v2(81.91,53.48) v2(81.94,52.21) v2(81.94,50.94) v2(81.94,49.67) v2(81.94,48.4) v2(82.08,69.46) v2(82.13,68.1) v2(82.18,118.78) v2(82.18,113.7) v2(82.19,66.71) v2(82.19,65.41) v2(83.04,99.95) v2(83.04,98.68) v2(83,97.41) v2(83.11,104.07) v2(83.08,102.54) v2(83.08,101.27) v2(83.07,60.86) v2(83.1,59.73) v2(83.11,58.61) v2(83.15,57.05) v2(83.18,56.03) v2(83.24,53.46) v2(83.27,52.18) v2(83.27,50.91) v2(83.27,49.64) v2(83.27,48.37) v2(83.27,47.1) v2(83.42,41.07) v2(83.45,79.26) v2(83.46,77.74) v2(83.46,76.47) v2(83.46,75.2) v2(83.46,73.73) v2(83.46,72.46) v2(83.46,71.19) v2(83.49,69.48) v2(83.55,68.13) v2(83.61,39.47) v2(83.61,37.57) v2(83.61,32.49) v2(83.69,66.71) v2(83.69,65.44) v2(83.72,64.17) v2(84.38,80.47) v2(84.63,102.54) v2(84.63,101.27) v2(84.58,99.95) v2(84.58,98.68) v2(84.55,97.41) v2(84.59,59.7) v2(84.61,58.58) v2(84.66,104.07) v2(84.65,57.02) v2(84.68,56) v2(84.74,53.43) v2(84.76,52.16) v2(84.76,50.89) v2(84.76,49.62) v2(84.76,48.35) v2(84.76,47.08) v2(84.76,45.81) v2(85.01,79.26) v2(85.01,77.85) v2(84.99,76.45) v2(84.99,75.18) v2(85.02,69.48) v2(85.07,73.84) v2(85.07,72.57) v2(85.07,71.3) v2(85.07,68.13) v2(85.19,66.69) v2(85.19,65.41) v2(85.22,64.14) v2(85.23,62.84) v2(85.32,61.62) v2(86,91.24) v2(86.02,58.61) v2(86.12,93.73) v2(86.05,92.47) v2(86.06,57.05) v2(86.09,56.03) v2(86.06,41.02) v2(86.23,102.56) v2(86.23,101.29) v2(86.18,99.97) v2(86.18,98.7) v2(86.15,97.43) v2(86.15,96.27) v2(86.15,95) v2(86.15,53.46) v2(86.18,52.18) v2(86.18,50.91) v2(86.18,49.64) v2(86.18,48.37) v2(86.18,47.1) v2(86.18,45.83) v2(86.26,104.09) v2(86.26,39.42) v2(86.26,37.53) v2(86.54,62.87) v2(86.65,61.59) v2(86.7,60.28) v2(86.79,75.12) v2(86.83,73.4) v2(86.88,79.31) v2(86.87,77.79) v2(86.87,76.55) v2(86.87,71.63) v2(87.26,118.78) v2(87.26,113.7) v2(87.33,57.05) v2(87.36,56.03) v2(87.42,53.46) v2(87.45,52.18) v2(87.45,50.91) v2(87.45,49.64) v2(87.45,48.37) v2(87.45,47.1) v2(87.45,45.83) v2(87.6,92.47) v2(87.57,91.22) v2(87.73,99.97) v2(87.73,98.7) v2(87.7,97.43) v2(87.7,96.27) v2(87.7,95) v2(87.66,93.73) v2(87.81,104.09) v2(87.77,102.55) v2(87.77,101.28) v2(87.93,60.31) v2(87.96,62.9) v2(87.96,61.6) v2(88.43,79.29) v2(88.43,77.85) v2(88.46,76.5) v2(88.46,75.23) v2(88.49,74.02) v2(89.29,92.48) v2(89.25,91.22) v2(89.42,99.98) v2(89.42,98.71) v2(89.39,97.45) v2(89.39,96.28) v2(89.39,95.01) v2(89.35,93.75) v2(89.5,104.1) v2(89.46,102.57) v2(89.46,101.3) v2(89.98,79.26) v2(89.95,77.82) v2(90.09,76.55) v2(90.12,75.25) v2(90.15,74.03) v2(90.2,40.97) v2(90.24,121.68) v2(90.24,120.41) v2(90.24,118.8) v2(90.4,37.47) v2(90.4,32.39) v2(91.03,91.22) v2(91.13,93.75) v2(91.06,92.48) v2(91.2,99.98) v2(91.2,98.71) v2(91.16,97.45) v2(91.16,96.28) v2(91.16,95.01) v2(91.27,104.1) v2(91.24,102.57) v2(91.24,101.3) v2(91.48,121.69) v2(91.48,120.42) v2(91.5,118.72) v2(92.81,91.22) v2(92.91,93.75) v2(92.84,92.48) v2(93.02,102.57) v2(93.02,101.3) v2(92.98,99.98) v2(92.98,98.71) v2(92.94,97.45) v2(92.94,96.28) v2(92.94,95.01) v2(93.05,104.1) v2(94.2,118.09) v2(94.2,113.01) v2(94.51,91.22) v2(94.61,93.75) v2(94.54,92.48) v2(94.72,102.57) v2(94.72,101.3) v2(94.67,99.98) v2(94.67,98.71) v2(94.64,97.45) v2(94.64,96.28) v2(94.64,95.01) v2(94.75,104.1) v2(95.26,40.95) v2(95.48,37.47) v2(95.48,32.39) v2(96.21,91.22) v2(96.31,93.75) v2(96.24,92.48) v2(96.42,102.57) v2(96.42,101.3) v2(96.37,99.98) v2(96.37,98.71) v2(96.34,97.45) v2(96.34,96.28) v2(96.34,95.01) v2(96.45,104.1) v2(97.91,91.22) v2(98.01,93.75) v2(97.94,92.48) v2(98.12,102.57) v2(98.12,101.3) v2(98.07,99.98) v2(98.07,98.71) v2(98.04,97.45) v2(98.04,96.28) v2(98.04,95.01) v2(98.15,104.1) v2(99.28,118.09) v2(99.28,113.01) v2(99.6,99.98) v2(99.6,98.71) v2(99.57,97.45) v2(99.68,104.1) v2(99.65,102.57) v2(99.65,101.3) v2(102.74,121.72) v2(102.74,120.45) v2(102.74,118.85) v2(103.98,121.74) v2(103.98,120.47) v2(104,118.77) v2(105.43,52.18) v2(105.43,50.91) v2(106.7,52.18) v2(107.2,118.88) v2(107.2,113.8) v2(112.28,118.88) v2(112.28,113.8) v2(115.56,121.76) v2(115.56,120.49) v2(115.56,118.88) v2(116.62,103.87) v2(116.59,102.34) v2(116.59,101.07) v2(116.55,99.75) v2(116.55,98.48) v2(116.8,121.77) v2(116.8,120.5) v2(116.82,118.8) v2(117.35,137.67) v2(117.35,132.59) v2(117.35,127.51) v2(117.35,5.59) v2(118.03,97.31) v2(118.03,96.04) v2(117.99,94.72) v2(117.99,93.45) v2(118.04,92.15) v2(118.13,102.34) v2(118.13,101.07) v2(118.09,99.75) v2(118.09,98.48) v2(118.17,103.87) v2(119.64,97.33) v2(119.64,96.06) v2(119.59,94.74) v2(119.59,93.47) v2(119.57,92.15) v2(119.74,102.35) v2(119.74,101.08) v2(119.69,99.77) v2(119.69,98.5) v2(119.81,118.78) v2(119.81,113.7) v2(119.77,103.89) v2(121.1,92.15) v2(121.09,70.27) v2(121.09,67.76) v2(121.09,62.8) v2(121.04,59.17) v2(121.09,56.11) v2(121.18,97.32) v2(121.18,96.05) v2(121.14,94.74) v2(121.14,93.47) v2(121.32,103.89) v2(121.28,102.35) v2(121.28,101.08) v2(121.24,99.76) v2(121.24,98.49) v2(121.65,72.29) v2(122.43,137.67) v2(122.43,127.51) v2(122.43,15.75) v2(122.43,10.67) v2(122.43,5.59) v2(122.83,95.88) v2(122.83,94.61) v2(122.83,93.52) v2(122.93,99.78) v2(122.93,98.51) v2(122.87,97.2) v2(123.01,103.9) v2(122.97,102.37) v2(122.97,101.1) v2(124.63,94.72) v2(124.71,99.78) v2(124.71,98.51) v2(124.7,97.34) v2(124.66,96.02) v2(124.78,103.9) v2(124.75,102.37) v2(124.75,101.1) v2(124.89,118.78) v2(124.89,113.7) v2(124.97,53.52) v2(125.11,52.18) v2(125.11,50.91) v2(125.11,49.64) v2(125.63,92.09) v2(126.53,102.37) v2(126.53,101.1) v2(126.49,99.78) v2(126.49,98.51) v2(126.46,97.35) v2(126.56,103.9) v2(126.63,93.22) v2(126.7,92.05) v2(127.51,137.67) v2(127.51,132.59) v2(127.51,127.51) v2(127.51,15.75) v2(128.23,102.37) v2(128.23,101.1) v2(128.18,99.78) v2(128.18,98.51) v2(128.26,103.9) v2(128.37,122.01) v2(128.37,120.74) v2(128.37,119.13) v2(129.62,122.02) v2(129.62,120.75) v2(129.63,119.05) v2(132.32,118.98) v2(132.32,113.9) v2(132.59,137.67) v2(132.59,132.59) v2(132.59,127.51) v2(132.59,15.75) v2(137.23,42.79) v2(137.4,118.98) v2(137.4,113.9) v2(137.53,32.59) v2(137.67,137.67) v2(137.67,132.59) v2(137.67,127.51) v2(137.67,15.75) v2(137.76,37.63) v2(140.04,121.79) v2(140.04,120.52) v2(140.04,118.91) v2(141.28,121.8) v2(141.28,120.53) v2(141.3,118.83) v2(142.31,42.79) v2(142.61,37.67) v2(142.61,32.59) v2(142.75,137.67) v2(142.75,127.51) v2(142.75,15.75) v2(142.75,10.67) v2(142.75,5.59) v2(143.09,52.18) v2(143.09,50.91) v2(143.09,49.64) v2(143.09,48.37) v2(143.09,47.1) v2(143.09,45.83) v2(144.04,119.08) v2(144.04,114) v2(144.36,52.18) v2(144.36,50.91) v2(144.36,49.64) v2(144.36,48.37) v2(144.36,47.1) v2(144.36,45.83) v2(147.08,42.89) v2(147.38,37.77) v2(147.38,32.69) v2(147.83,81.79) v2(147.83,46.23) v2(147.83,15.75) v2(147.83,10.67) v2(147.83,5.59) v2(148.22,52.32) v2(148.33,79.37) v2(148.3,72.78) v2(148.25,51.21) v2(148.35,77.68) v2(148.35,75.9) v2(148.35,74.35) v2(149.12,119.08) v2(149.12,114) v2(149.11,102.64) v2(149.11,101.37) v2(149.07,100.05) v2(149.07,98.78) v2(149.15,104.17) v2(149.52,51.27) v2(149.6,53.53) v2(149.58,52.32) v2(149.73,71.25) v2(149.66,40.61) v2(149.83,79.46) v2(149.82,75.93) v2(149.8,74.31) v2(149.76,72.74) v2(149.76,70.01) v2(149.86,77.7) v2(150.23,68.8) v2(150.29,66.88) v2(150.34,65.31) v2(150.34,63.53) v2(150.36,61.46) v2(150.41,60.29) v2(150.38,58.97) v2(150.34,57.57) v2(150.81,94.06) v2(150.81,92.79) v2(150.78,91.77) v2(150.91,100.11) v2(150.91,98.84) v2(150.85,95.38) v2(150.9,52.37) v2(150.99,104.24) v2(150.96,102.7) v2(150.96,101.43) v2(150.96,54.78) v2(150.96,53.53) v2(151.23,75.95) v2(151.23,74.25) v2(151.19,72.68) v2(151.27,79.47) v2(151.24,77.66) v2(151.29,71.23) v2(151.56,66.88) v2(151.61,65.31) v2(151.61,63.53) v2(151.63,61.46) v2(151.68,60.29) v2(151.67,58.99) v2(152.15,121.72) v2(152.15,120.45) v2(152.15,118.85) v2(152.16,42.89) v2(152.32,54.78) v2(152.29,53.59) v2(152.25,40.78) v2(152.36,56.14) v2(152.46,37.77) v2(152.46,32.69) v2(152.54,79.44) v2(152.57,77.66) v2(152.59,75.96) v2(152.6,74.28) v2(152.56,72.71) v2(152.73,102.7) v2(152.73,101.43) v2(152.69,100.11) v2(152.69,98.84) v2(152.69,95.35) v2(152.65,94.03) v2(152.65,92.76) v2(152.65,91.74) v2(152.77,104.24) v2(152.82,65.27) v2(152.82,63.49) v2(152.77,48.68) v2(152.91,137.67) v2(152.91,61.47) v2(152.91,46.23) v2(152.91,15.75) v2(152.91,10.67) v2(152.91,5.59) v2(152.98,60.39) v2(153.39,121.74) v2(153.39,120.47) v2(153.41,118.77) v2(153.62,57.72) v2(153.63,56.14) v2(153.65,54.83) v2(153.82,75.93) v2(153.8,72.72) v2(153.88,79.42) v2(153.88,77.65) v2(153.84,74.29) v2(154.14,65.22) v2(154.14,63.44) v2(154.43,94.03) v2(154.43,92.76) v2(154.41,91.67) v2(154.51,102.7) v2(154.51,101.43) v2(154.47,100.11) v2(154.47,98.84) v2(154.47,95.35) v2(154.55,104.24) v2(154.71,42.64) v2(154.8,40.74) v2(154.97,118.29) v2(154.97,113.21) v2(155.12,75.93) v2(155.09,74.27) v2(155.04,72.7) v2(155.05,52.18) v2(155.05,50.91) v2(155.05,49.64) v2(155.05,48.37) v2(155.05,47.1) v2(155.05,45.83) v2(155.15,79.42) v2(155.15,77.65) v2(155.23,59.24) v2(155.32,57.83) v2(155.34,56.16) v2(156.03,100.25) v2(156.03,98.98) v2(156.11,104.37) v2(156.07,102.84) v2(156.07,101.57) v2(156.32,52.18) v2(156.32,50.91) v2(156.32,49.64) v2(156.32,48.37) v2(156.32,47.1) v2(156.32,45.83) v2(157.73,94.03) v2(157.73,92.76) v2(157.81,102.7) v2(157.81,101.43) v2(157.77,100.11) v2(157.77,98.84) v2(157.77,95.35) v2(157.82,91.81) v2(157.85,104.24) v2(157.99,137.67) v2(157.99,132.59) v2(157.99,127.51) v2(157.99,71.63) v2(157.99,15.75) v2(157.99,10.67) v2(157.99,5.59) v2(158.95,42.79) v2(159.25,37.67) v2(159.25,32.59) v2(159.51,94.03) v2(159.51,92.76) v2(159.47,91.74) v2(159.63,104.24) v2(159.59,102.7) v2(159.59,101.43) v2(159.55,100.11) v2(159.55,98.84) v2(159.55,95.35) v2(160.05,118.29) v2(160.05,113.21) v2(161.21,95.38) v2(161.17,94.06) v2(161.17,92.79) v2(161.14,91.77) v2(161.33,100.11) v2(161.33,98.84) v2(161.4,104.24) v2(161.37,102.7) v2(161.37,101.43) v2(163.03,100.11) v2(163.03,98.84) v2(163.07,137.67) v2(163.07,132.59) v2(163.07,127.51) v2(163.1,104.24) v2(163.07,102.7) v2(163.07,101.43) v2(163.07,15.75) v2(164.01,121.61) v2(164.01,120.34) v2(164.01,118.74) v2(164.03,42.79) v2(164.33,37.67) v2(164.33,32.59) v2(165.25,121.63) v2(165.25,120.36) v2(165.26,118.66) v2(167.08,119.08) v2(167.08,114) v2(168.15,137.67) v2(168.15,132.59) v2(168.15,127.51) v2(168.15,15.75) v2(171.76,42.89) v2(172.05,37.77) v2(172.05,32.69) v2(172.16,119.08) v2(172.16,114) v2(173.23,137.67) v2(173.23,132.59) v2(173.23,127.51) v2(173.23,15.75) v2(173.23,10.67) v2(173.23,5.59) v2(174.25,53.48) v2(174.3,52.18) v2(174.3,50.91) v2(174.3,49.64) v2(174.3,48.37) v2(174.3,47.1) v2(174.3,45.83) v2(174.7,32.84) v2(175.57,52.18) v2(175.57,50.91) v2(175.57,49.64) v2(175.57,48.37) v2(175.57,47.1) v2(175.57,45.83) v2(175.82,121.47) v2(175.82,120.2) v2(175.82,118.59) v2(175.76,53.49) v2(176.84,42.89) v2(177.06,121.49) v2(177.06,120.22) v2(177.07,118.52) v2(177.11,53.5) v2(177.13,37.77) v2(177.13,32.69) v2(177.16,52.2) v2(177.16,50.9) v2(177.19,49.6) v2(177.19,48.42) v2(177.22,47.14) v2(178.31,137.67) v2(178.31,15.75) v2(178.31,10.67) v2(178.31,5.59) v2(178.52,53.52) v2(178.58,52.22) v2(178.58,50.92) v2(178.61,49.62) v2(178.61,48.43) v2(179.02,42.26) v2(179.02,40.48) v2(179.1,118.19) v2(179.1,113.11) v2(179.79,53.56) v2(179.85,52.26) v2(179.85,50.96) v2(179.96,78.63) v2(180.02,77.33) v2(180.05,75.89) v2(180.1,74.42) v2(180.1,73.01) v2(180.13,71.65) v2(180.34,42.22) v2(180.34,40.44) v2(180.44,69.91) v2(180.48,68.28) v2(180.46,66.78) v2(180.47,65.38) v2(180.44,61.5) v2(180.47,59.98) v2(180.5,58.31) v2(180.53,56.84) v2(180.48,32.93) v2(180.56,55.45) v2(180.6,54.08) v2(181.22,80.45) v2(181.21,78.66) v2(181.26,77.36) v2(181.29,75.92) v2(181.35,74.45) v2(181.35,73.04) v2(181.38,71.68) v2(181.6,102.84) v2(181.6,101.57) v2(181.56,100.25) v2(181.56,98.98) v2(181.61,42.22) v2(181.61,40.44) v2(181.65,84.14) v2(181.65,82.29) v2(181.93,66.79) v2(181.96,69.91) v2(181.95,68.32) v2(181.94,63.15) v2(181.95,61.52) v2(181.98,59.99) v2(182.01,58.32) v2(182.04,56.85) v2(182.07,55.47) v2(182.11,54.1) v2(182.54,80.4) v2(182.54,78.62) v2(182.6,77.32) v2(182.63,75.88) v2(182.68,74.41) v2(182.68,73) v2(182.71,71.64) v2(182.81,44.45) v2(182.93,42.99) v2(183.17,63.1) v2(183.23,37.86) v2(183.23,32.78) v2(183.34,100.25) v2(183.34,98.98) v2(183.34,95.48) v2(183.29,94.16) v2(183.29,92.89) v2(183.28,69.87) v2(183.3,68.32) v2(183.3,66.83) v2(183.3,64.5) v2(183.3,61.53) v2(183.33,60.01) v2(183.38,102.84) v2(183.38,101.57) v2(183.39,91.95) v2(183.44,82.85) v2(183.39,81.79) v2(183.35,58.34) v2(183.38,56.87) v2(183.41,55.48) v2(183.39,15.75) v2(183.39,10.67) v2(183.39,5.59) v2(183.46,84.06) v2(183.81,80.4) v2(183.81,78.62) v2(183.87,77.32) v2(183.9,75.88) v2(183.95,74.41) v2(183.95,73) v2(183.98,71.64) v2(184,52.18) v2(184,50.91) v2(184,49.64) v2(184,48.37) v2(184,47.1) v2(184,45.83) v2(183.98,44.51) v2(184.01,43.36) v2(184.06,41.8) v2(184.07,40.63) v2(184.18,118.19) v2(184.18,113.11) v2(184.27,64.46) v2(184.34,63.13) v2(184.5,68.34) v2(184.55,69.87) v2(184.56,66.89) v2(184.56,61.49) v2(184.58,59.96) v2(184.61,58.3) v2(184.64,56.83) v2(185.01,32.97) v2(185.11,100.25) v2(185.11,98.98) v2(185.11,95.48) v2(185.07,94.16) v2(185.07,92.89) v2(185.07,44.41) v2(185.11,43.32) v2(185.07,41.8) v2(185.07,40.66) v2(185.16,102.84) v2(185.16,101.57) v2(185.23,73) v2(185.14,47.11) v2(185.14,45.88) v2(185.25,71.64) v2(185.27,52.18) v2(185.27,50.91) v2(185.27,49.64) v2(185.27,48.37) v2(185.51,84.08) v2(185.47,82.91) v2(185.44,81.79) v2(186.5,73) v2(186.52,71.64) v2(187.67,121.32) v2(187.67,120.05) v2(187.67,118.44) v2(188.31,37.86) v2(188.31,32.78) v2(188.42,100.25) v2(188.42,98.98) v2(188.42,95.48) v2(188.37,94.16) v2(188.37,92.89) v2(188.47,137.67) v2(188.46,102.84) v2(188.46,101.57) v2(188.47,91.95) v2(188.47,15.75) v2(188.47,10.67) v2(188.47,5.59) v2(188.91,121.33) v2(188.91,120.06) v2(188.93,118.36) v2(190.24,102.84) v2(190.24,101.57) v2(190.19,100.25) v2(190.19,98.98) v2(190.19,95.48) v2(190.15,94.16) v2(190.15,92.89) v2(192.01,102.84) v2(192.01,101.57) v2(191.97,100.25) v2(191.97,98.98) v2(193.55,137.67) v2(193.55,132.59) v2(193.55,127.51) v2(193.55,15.75) v2(193.55,10.67) v2(193.55,5.59) v2(194.75,37.72) v2(194.75,32.64) v2(196.83,121.94) v2(196.83,116.86) v2(198.63,137.67) v2(198.63,132.59) v2(198.63,127.51) v2(198.63,15.75) v2(199.83,37.72) v2(199.83,32.64) v2(201.91,121.94) v2(201.91,116.86) v2(203.71,137.67) v2(203.71,132.59) v2(203.71,127.51) v2(203.71,30.99) v2(203.71,15.75) v2(206.13,38.75) v2(206.13,33.67) v2(208.79,137.67) v2(208.79,132.59) v2(208.79,127.51) v2(208.79,122.43) v2(208.79,112.27) v2(208.79,102.11) v2(208.79,81.79) v2(208.79,71.63) v2(208.79,61.47) v2(208.79,51.31) v2(208.79,46.23) v2(208.79,30.99) v2(208.79,15.75) v2(208.79,10.67) v2(208.79,5.59) v2(211.21,38.75) v2(211.21,33.67) v2(213.87,137.67) v2(213.87,132.59) v2(213.87,127.51) v2(213.87,122.43) v2(213.87,117.35) v2(213.87,107.19) v2(213.87,97.03) v2(213.87,91.95) v2(213.87,86.87) v2(213.87,81.79) v2(213.87,76.71) v2(213.87,71.63) v2(213.87,66.55) v2(213.87,61.47) v2(213.87,56.39) v2(213.87,51.31) v2(213.87,46.23) v2(213.87,41.15) v2(213.87,30.99) v2(213.87,15.75) v2(213.87,10.67) v2(213.87,5.59) v2(218.95,137.67) v2(218.95,132.59) v2(218.95,127.51) v2(218.95,122.43) v2(218.95,117.35) v2(218.95,112.27) v2(218.95,107.19) v2(218.95,102.11) v2(218.95,97.03) v2(218.95,91.95) v2(218.95,86.87) v2(218.95,81.79) v2(218.95,15.75) v2(218.95,10.67) v2(224.03,127.51) v2(224.03,122.43) v2(224.03,117.35) v2(224.03,112.27) v2(224.03,107.19) v2(224.03,15.75) v3(29.99,79.46) v3(29.99,79.08) v3(30.26,77.33) v3(30.26,75.63) v3(30.38,79.46) v3(30.38,79.08) v3(30.64,77.33) v3(30.64,75.63) v3(30.76,79.46) v3(30.76,79.08) v3(31.02,77.33) v3(31.02,75.63) v3(31.14,79.46) v3(31.14,79.08) v3(31.4,77.33) v3(31.4,75.63) v3(31.52,79.46) v3(31.52,79.08) v3(31.78,77.33) v3(31.78,75.63) v3(31.9,79.46) v3(31.9,79.08) v3(32.16,77.33) v3(32.16,75.63) v3(32.55,77.33) v3(32.55,75.63) v3(32.93,77.33) v3(32.93,75.63) v3(33.31,77.33) v3(33.31,75.63) v3(33.45,85.97) v3(34.87,95.34) v3(34.87,93.31) v3(34.87,89.25) v3(34.87,87.22) v3(34.97,85.98) v3(35.05,79) v3(35.38,95.34) v3(35.38,93.31) v3(35.38,89.25) v3(35.38,87.22) v3(35.55,79) v3(51.58,96.64) v3(51.58,95.75) v3(51.58,94.86) v3(51.58,93.06) v3(51.58,92.17) v3(51.58,91.28) v3(51.56,89.46) v3(51.56,88.58) v3(51.56,87.69) v3(52.09,96.64) v3(52.09,95.75) v3(52.09,94.86) v3(52.09,93.06) v3(52.09,92.17) v3(52.09,91.28) v3(52.07,89.46) v3(52.07,88.58) v3(52.07,87.69) v3(58.95,79.46) v3(58.95,79.08) v3(59.21,77.33) v3(59.21,75.63) v3(59.33,79.46) v3(59.33,79.08) v3(59.59,77.33) v3(59.59,75.63) v3(59.71,79.46) v3(59.71,79.08) v3(59.97,77.33) v3(59.97,75.63) v3(60.09,79.46) v3(60.09,79.08) v3(60.35,77.33) v3(60.35,75.63) v3(60.47,79.46) v3(60.47,79.08) v3(60.73,77.33) v3(60.73,75.63) v3(60.85,79.46) v3(60.85,79.08) v3(61.12,77.33) v3(61.12,75.63) v3(61.5,77.33) v3(61.5,75.63) v3(61.88,77.33) v3(61.88,75.63) v3(62.26,77.33) v3(62.26,75.63) v3(62.4,85.97) v3(63.82,95.34) v3(63.82,93.31) v3(63.82,89.25) v3(63.82,87.22) v3(63.92,85.98) v3(64,79) v3(64,77.48) v3(64,75.95) v3(64,74.43) v3(64,72.92) v3(64,71.38) v3(64.33,95.34) v3(64.33,93.31) v3(64.33,89.25) v3(64.33,87.22) v3(64.5,79) v3(64.5,77.48) v3(64.5,75.95) v3(64.5,74.43) v3(64.5,72.92) v3(64.5,71.38) v3(83.33,96.48) v3(83.33,95.59) v3(83.33,94.7) v3(83.33,92.85) v3(83.33,91.96) v3(83.36,91.24) v3(83.35,89.21) v3(83.35,88.32) v3(83.35,87.43) v3(83.84,96.48) v3(83.84,95.59) v3(83.84,94.7) v3(83.84,92.85) v3(83.84,91.96) v3(83.86,89.21) v3(83.86,88.32) v3(83.86,87.43) v3(94.51,79.46) v3(94.51,79.08) v3(94.78,77.33) v3(94.78,75.63) v3(94.89,79.46) v3(94.89,79.08) v3(95.16,77.33) v3(95.16,75.63) v3(95.27,79.46) v3(95.27,79.08) v3(95.54,77.33) v3(95.54,75.63) v3(95.65,79.46) v3(95.65,79.08) v3(95.92,77.33) v3(95.92,75.63) v3(96.03,79.46) v3(96.03,79.08) v3(96.3,77.33) v3(96.3,75.63) v3(96.42,79.46) v3(96.42,79.08) v3(96.68,77.33) v3(96.68,75.63) v3(97.06,77.33) v3(97.06,75.63) v3(97.44,77.33) v3(97.44,75.63) v3(97.82,77.33) v3(97.82,75.63) v3(97.96,85.97) v3(99.39,95.34) v3(99.39,93.31) v3(99.39,89.25) v3(99.39,87.22) v3(99.48,85.98) v3(99.56,79) v3(99.56,77.48) v3(99.56,75.95) v3(99.56,74.43) v3(99.56,72.92) v3(99.56,71.38) v3(99.89,95.34) v3(99.89,93.31) v3(99.89,89.25) v3(99.89,87.22) v3(100.07,79) v3(100.07,77.48) v3(100.07,75.95) v3(100.07,74.43) v3(100.07,72.92) v3(100.07,71.38) v3(100.06,38.24) v3(103.28,32.73) v3(103.28,32.22) v3(103.28,31.71) v3(104.74,34.48) v3(104.74,33.72) v3(106.86,36.98) v3(109.44,36.09) v3(116.09,96.65) v3(116.09,95.76) v3(116.09,94.87) v3(116.08,93.06) v3(116.08,92.17) v3(116.08,91.29) v3(116.08,89.46) v3(116.08,88.58) v3(116.08,87.69) v3(116.6,96.65) v3(116.6,95.76) v3(116.6,94.87) v3(116.59,93.06) v3(116.59,92.17) v3(116.59,91.29) v3(116.59,89.46) v3(116.59,88.58) v3(116.59,87.69) v3(120.05,42.6) v3(123.46,79.46) v3(123.46,79.08) v3(123.73,77.33) v3(123.73,75.63) v3(123.84,79.46) v3(123.84,79.08) v3(123.99,44.06) v3(124.11,77.33) v3(124.11,75.63) v3(124.22,79.46) v3(124.22,79.08) v3(124.49,77.33) v3(124.49,75.63) v3(124.6,79.46) v3(124.6,79.08) v3(124.57,41.21) v3(124.57,40.53) v3(124.87,77.33) v3(124.87,75.63) v3(124.99,79.46) v3(124.99,79.08) v3(125.25,77.33) v3(125.25,75.63) v3(125.27,36.91) v3(125.27,36.4) v3(125.27,34.8) v3(125.26,32.98) v3(125.37,79.46) v3(125.37,79.08) v3(125.63,77.33) v3(125.63,75.63) v3(125.67,32.98) v3(126.01,77.33) v3(126.01,75.63) v3(126.39,77.33) v3(126.39,75.63) v3(126.77,77.33) v3(126.77,75.63) v3(126.91,85.97) v3(127.2,35.89) v3(128.34,95.34) v3(128.34,93.31) v3(128.34,89.25) v3(128.34,87.22) v3(128.25,43.38) v3(128.25,42.01) v3(128.43,85.98) v3(128.51,79) v3(128.51,77.48) v3(128.51,75.95) v3(128.51,74.43) v3(128.51,72.92) v3(128.51,71.38) v3(128.84,95.34) v3(128.84,93.31) v3(128.84,89.25) v3(128.84,87.22) v3(129.02,79) v3(129.02,77.48) v3(129.02,75.95) v3(129.02,74.43) v3(129.02,72.92) v3(129.02,71.38) v3(130.06,35.47) v3(130.06,34.84) v3(147.99,96.6) v3(147.99,95.71) v3(147.99,94.82) v3(147.99,93.02) v3(147.99,92.13) v3(147.97,91.27) v3(147.99,89.4) v3(147.99,88.51) v3(147.99,87.62) v3(148.49,96.6) v3(148.49,95.71) v3(148.49,94.82) v3(148.49,93.02) v3(148.5,91.27) v3(148.49,89.4) v3(148.49,88.51) v3(148.49,87.62) v3(159.03,79.46) v3(159.03,79.08) v3(159.29,77.33) v3(159.29,75.63) v3(159.41,79.46) v3(159.41,79.08) v3(159.67,77.33) v3(159.67,75.63) v3(159.79,79.46) v3(159.79,79.08) v3(160.05,77.33) v3(160.05,75.63) v3(160.17,79.46) v3(160.17,79.08) v3(160.43,77.33) v3(160.43,75.63) v3(160.55,79.46) v3(160.55,79.08) v3(160.82,77.33) v3(160.82,75.63) v3(160.93,79.46) v3(160.93,79.08) v3(161.2,77.33) v3(161.2,75.63) v3(161.58,77.33) v3(161.58,75.63) v3(161.96,77.33) v3(161.96,75.63) v3(162.34,77.33) v3(162.34,75.63) v3(162.48,85.97) v3(163.9,95.34) v3(163.9,93.31) v3(163.9,89.25) v3(163.9,87.22) v3(164,85.98) v3(164.08,79) v3(164.08,77.48) v3(164.08,75.95) v3(164.08,74.43) v3(164.08,72.92) v3(164.08,71.38) v3(164.41,95.34) v3(164.41,93.31) v3(164.41,89.25) v3(164.41,87.22) v3(164.59,79) v3(164.59,77.48) v3(164.59,75.95) v3(164.59,74.43) v3(164.59,72.92) v3(164.59,71.38) v3(180.56,96.67) v3(180.56,95.78) v3(180.56,94.89) v3(180.59,93.08) v3(180.59,92.19) v3(180.59,91.3) v3(180.59,89.46) v3(180.59,88.58) v3(180.59,87.69) v3(181.07,96.67) v3(181.07,95.78) v3(181.07,94.89) v3(181.1,93.08) v3(181.1,92.19) v3(181.1,91.3) v3(181.1,89.46) v3(181.1,88.58) v3(181.1,87.69) v3(187.98,79.46) v3(187.98,79.08) v3(188.24,77.33) v3(188.24,75.63) v3(188.36,79.46) v3(188.36,79.08) v3(188.62,77.33) v3(188.62,75.63) v3(188.74,79.46) v3(188.74,79.08) v3(189,77.33) v3(189,75.63) v3(189.12,79.46) v3(189.12,79.08) v3(189.39,77.33) v3(189.39,75.63) v3(189.5,79.46) v3(189.5,79.08) v3(189.77,77.33) v3(189.77,75.63) v3(189.88,79.46) v3(189.88,79.08) v3(190.15,77.33) v3(190.15,75.63) v3(190.53,77.33) v3(190.53,75.63) v3(190.91,77.33) v3(190.91,75.63) v3(191.29,77.33) v3(191.29,75.63) v3(191.43,85.97) v3(192.85,95.34) v3(192.85,93.31) v3(192.85,89.25) v3(192.85,87.22) v3(192.95,85.98) v3(193.03,79) v3(193.03,77.48) v3(193.03,75.95) v3(193.03,74.43) v3(193.03,72.92) v3(193.03,71.38) v3(193.36,95.34) v3(193.36,93.31) v3(193.36,89.25) v3(193.36,87.22) v3(193.54,79) v3(193.54,77.48) v3(193.54,75.95) v3(193.54,74.43) v3(193.54,72.92) v3(193.54,71.38) v3(209.53,96.68) v3(209.53,95.79) v3(209.53,94.9) v3(209.55,93.08) v3(209.55,92.19) v3(209.55,91.3) v3(209.54,89.46) v3(209.54,88.58) v3(209.54,87.69) v3(210.04,96.68) v3(210.04,95.79) v3(210.04,94.9) v3(210.05,93.08) v3(210.05,92.19) v3(210.05,91.3) v3(210.05,89.46) v3(210.05,88.58) v3(210.05,87.69) v3(217.47,76.1) v3(217.47,75.59) v3(217.47,70.3) v3(217.47,69.79)
